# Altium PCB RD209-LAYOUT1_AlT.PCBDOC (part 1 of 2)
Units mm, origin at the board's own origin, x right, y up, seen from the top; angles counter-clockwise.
Board outline 152.4 x 152.4 mm, 4 copper layers (TOP, Mid-Layer 1, Mid-Layer 2, BOTTOM), stack 0.711 mm thick; 246 components, 168 nets, 761 pads, 266 vias.
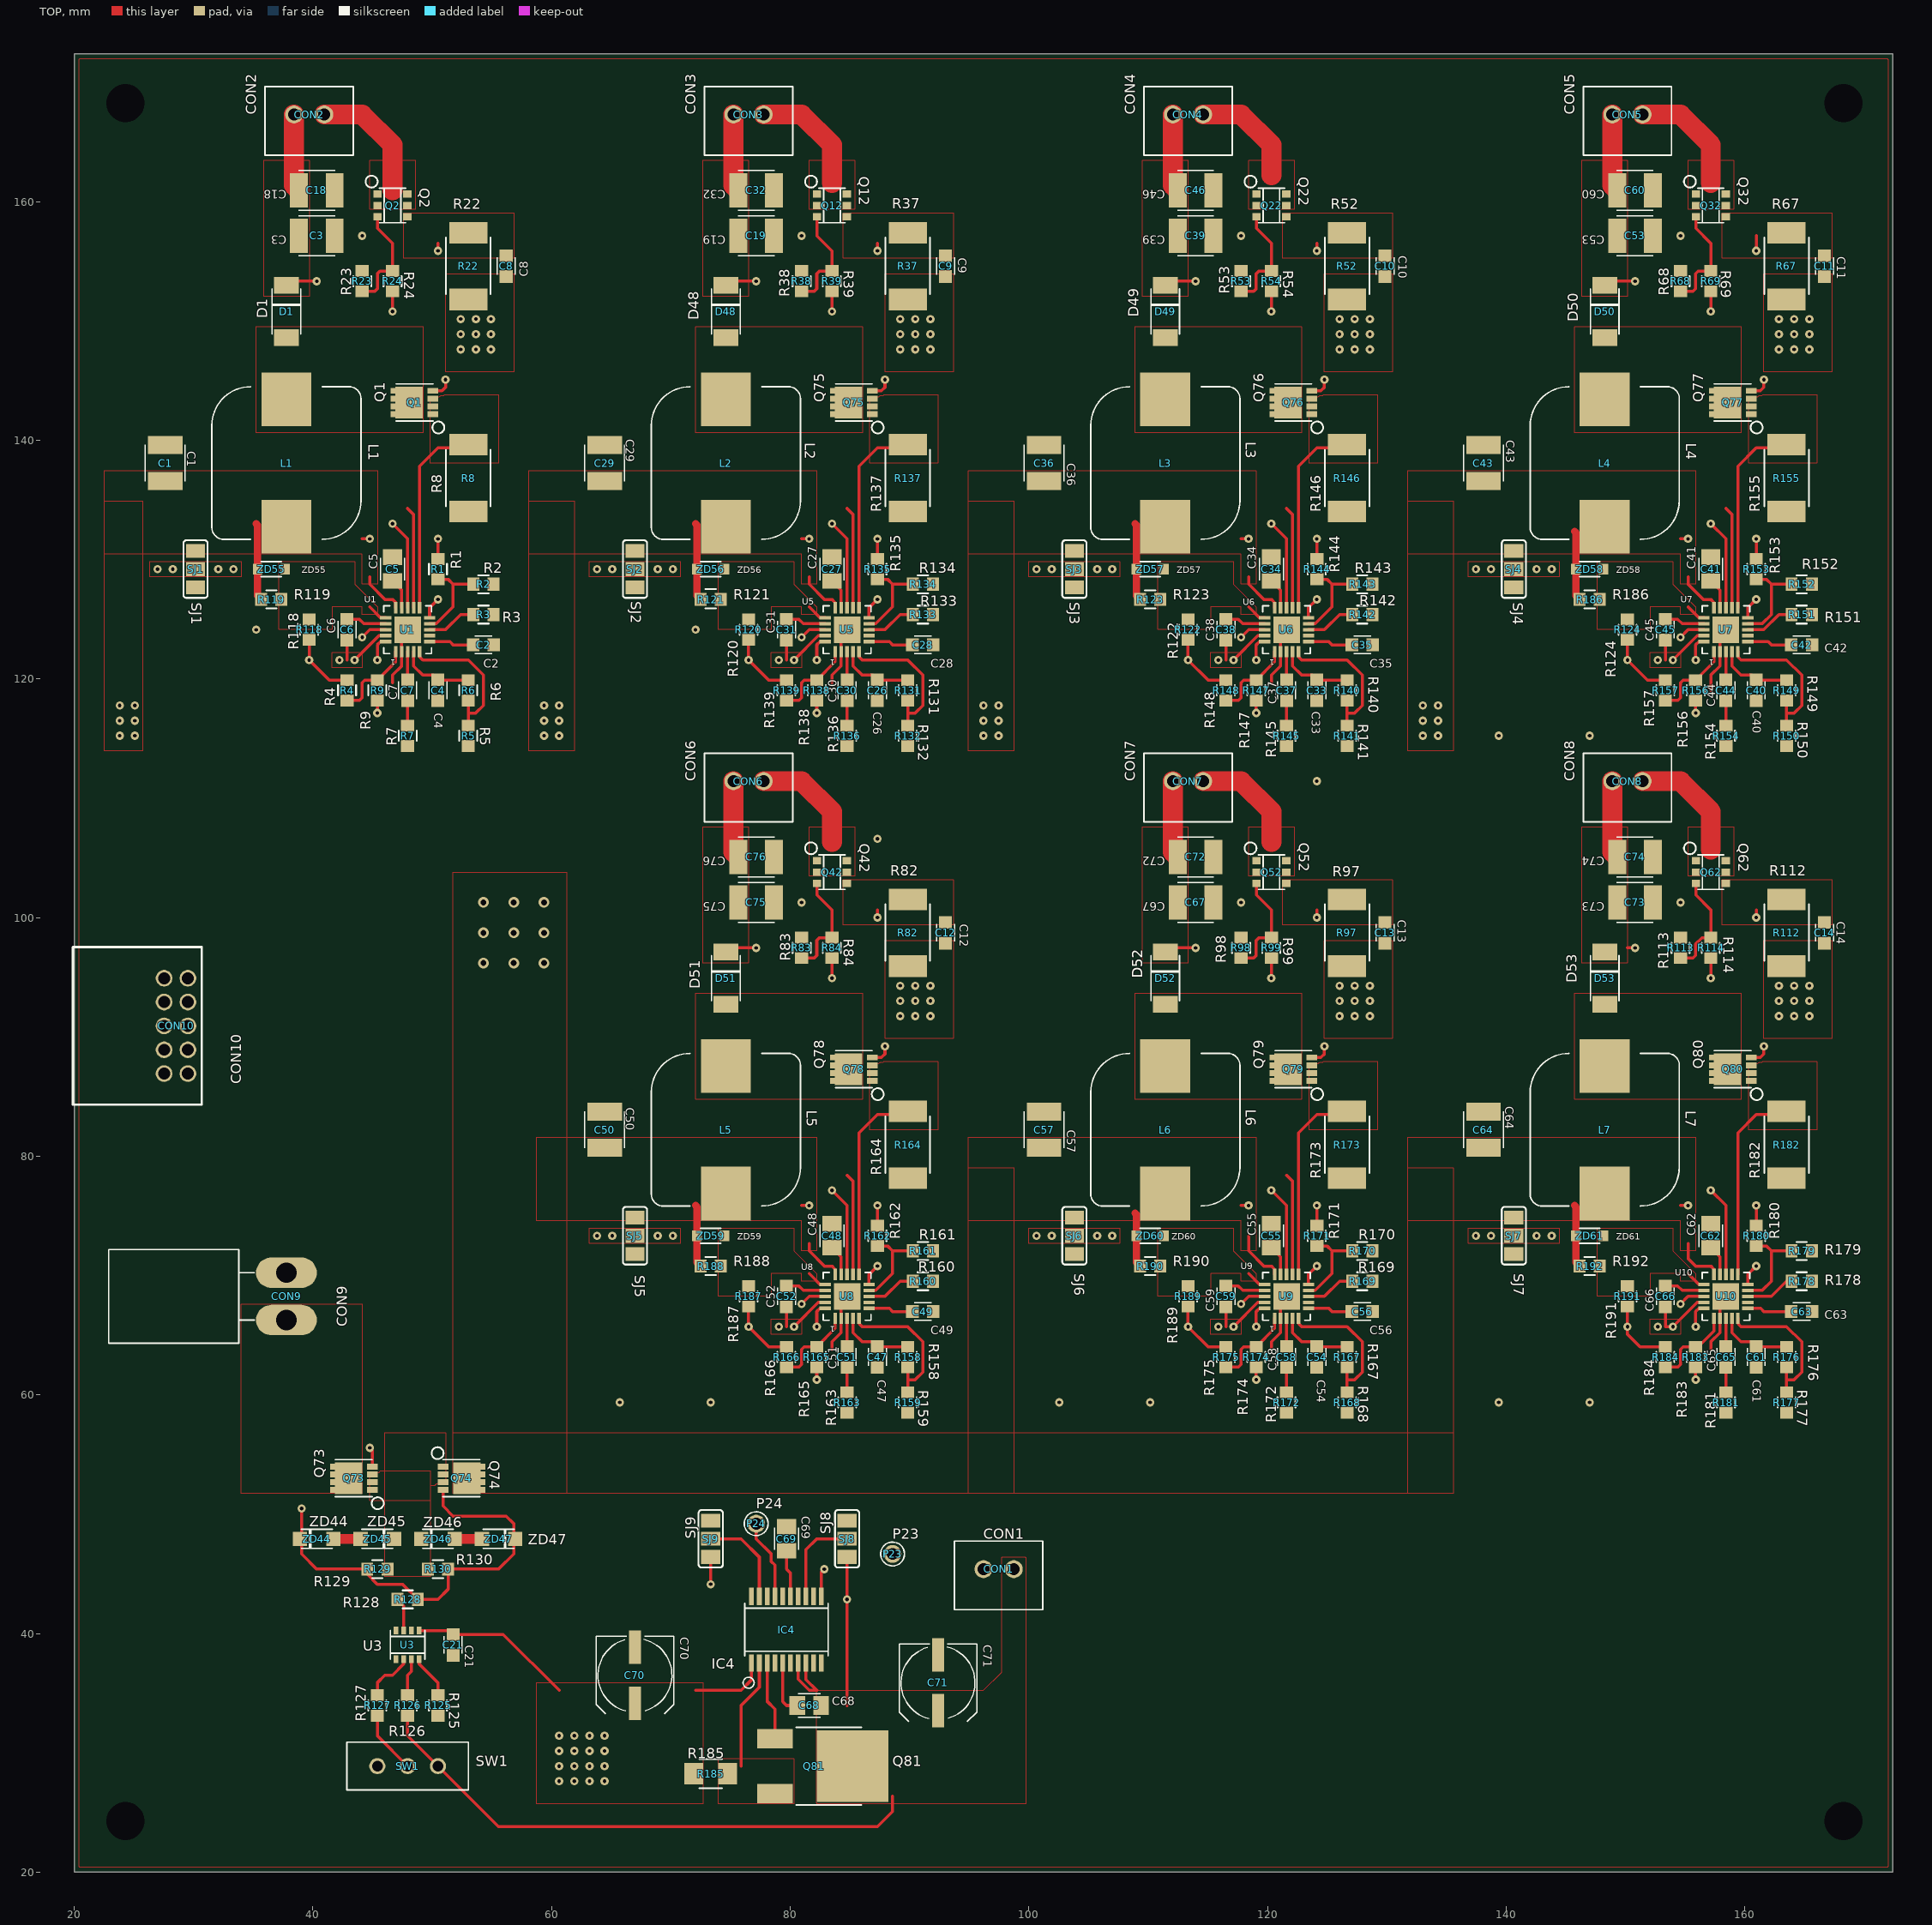
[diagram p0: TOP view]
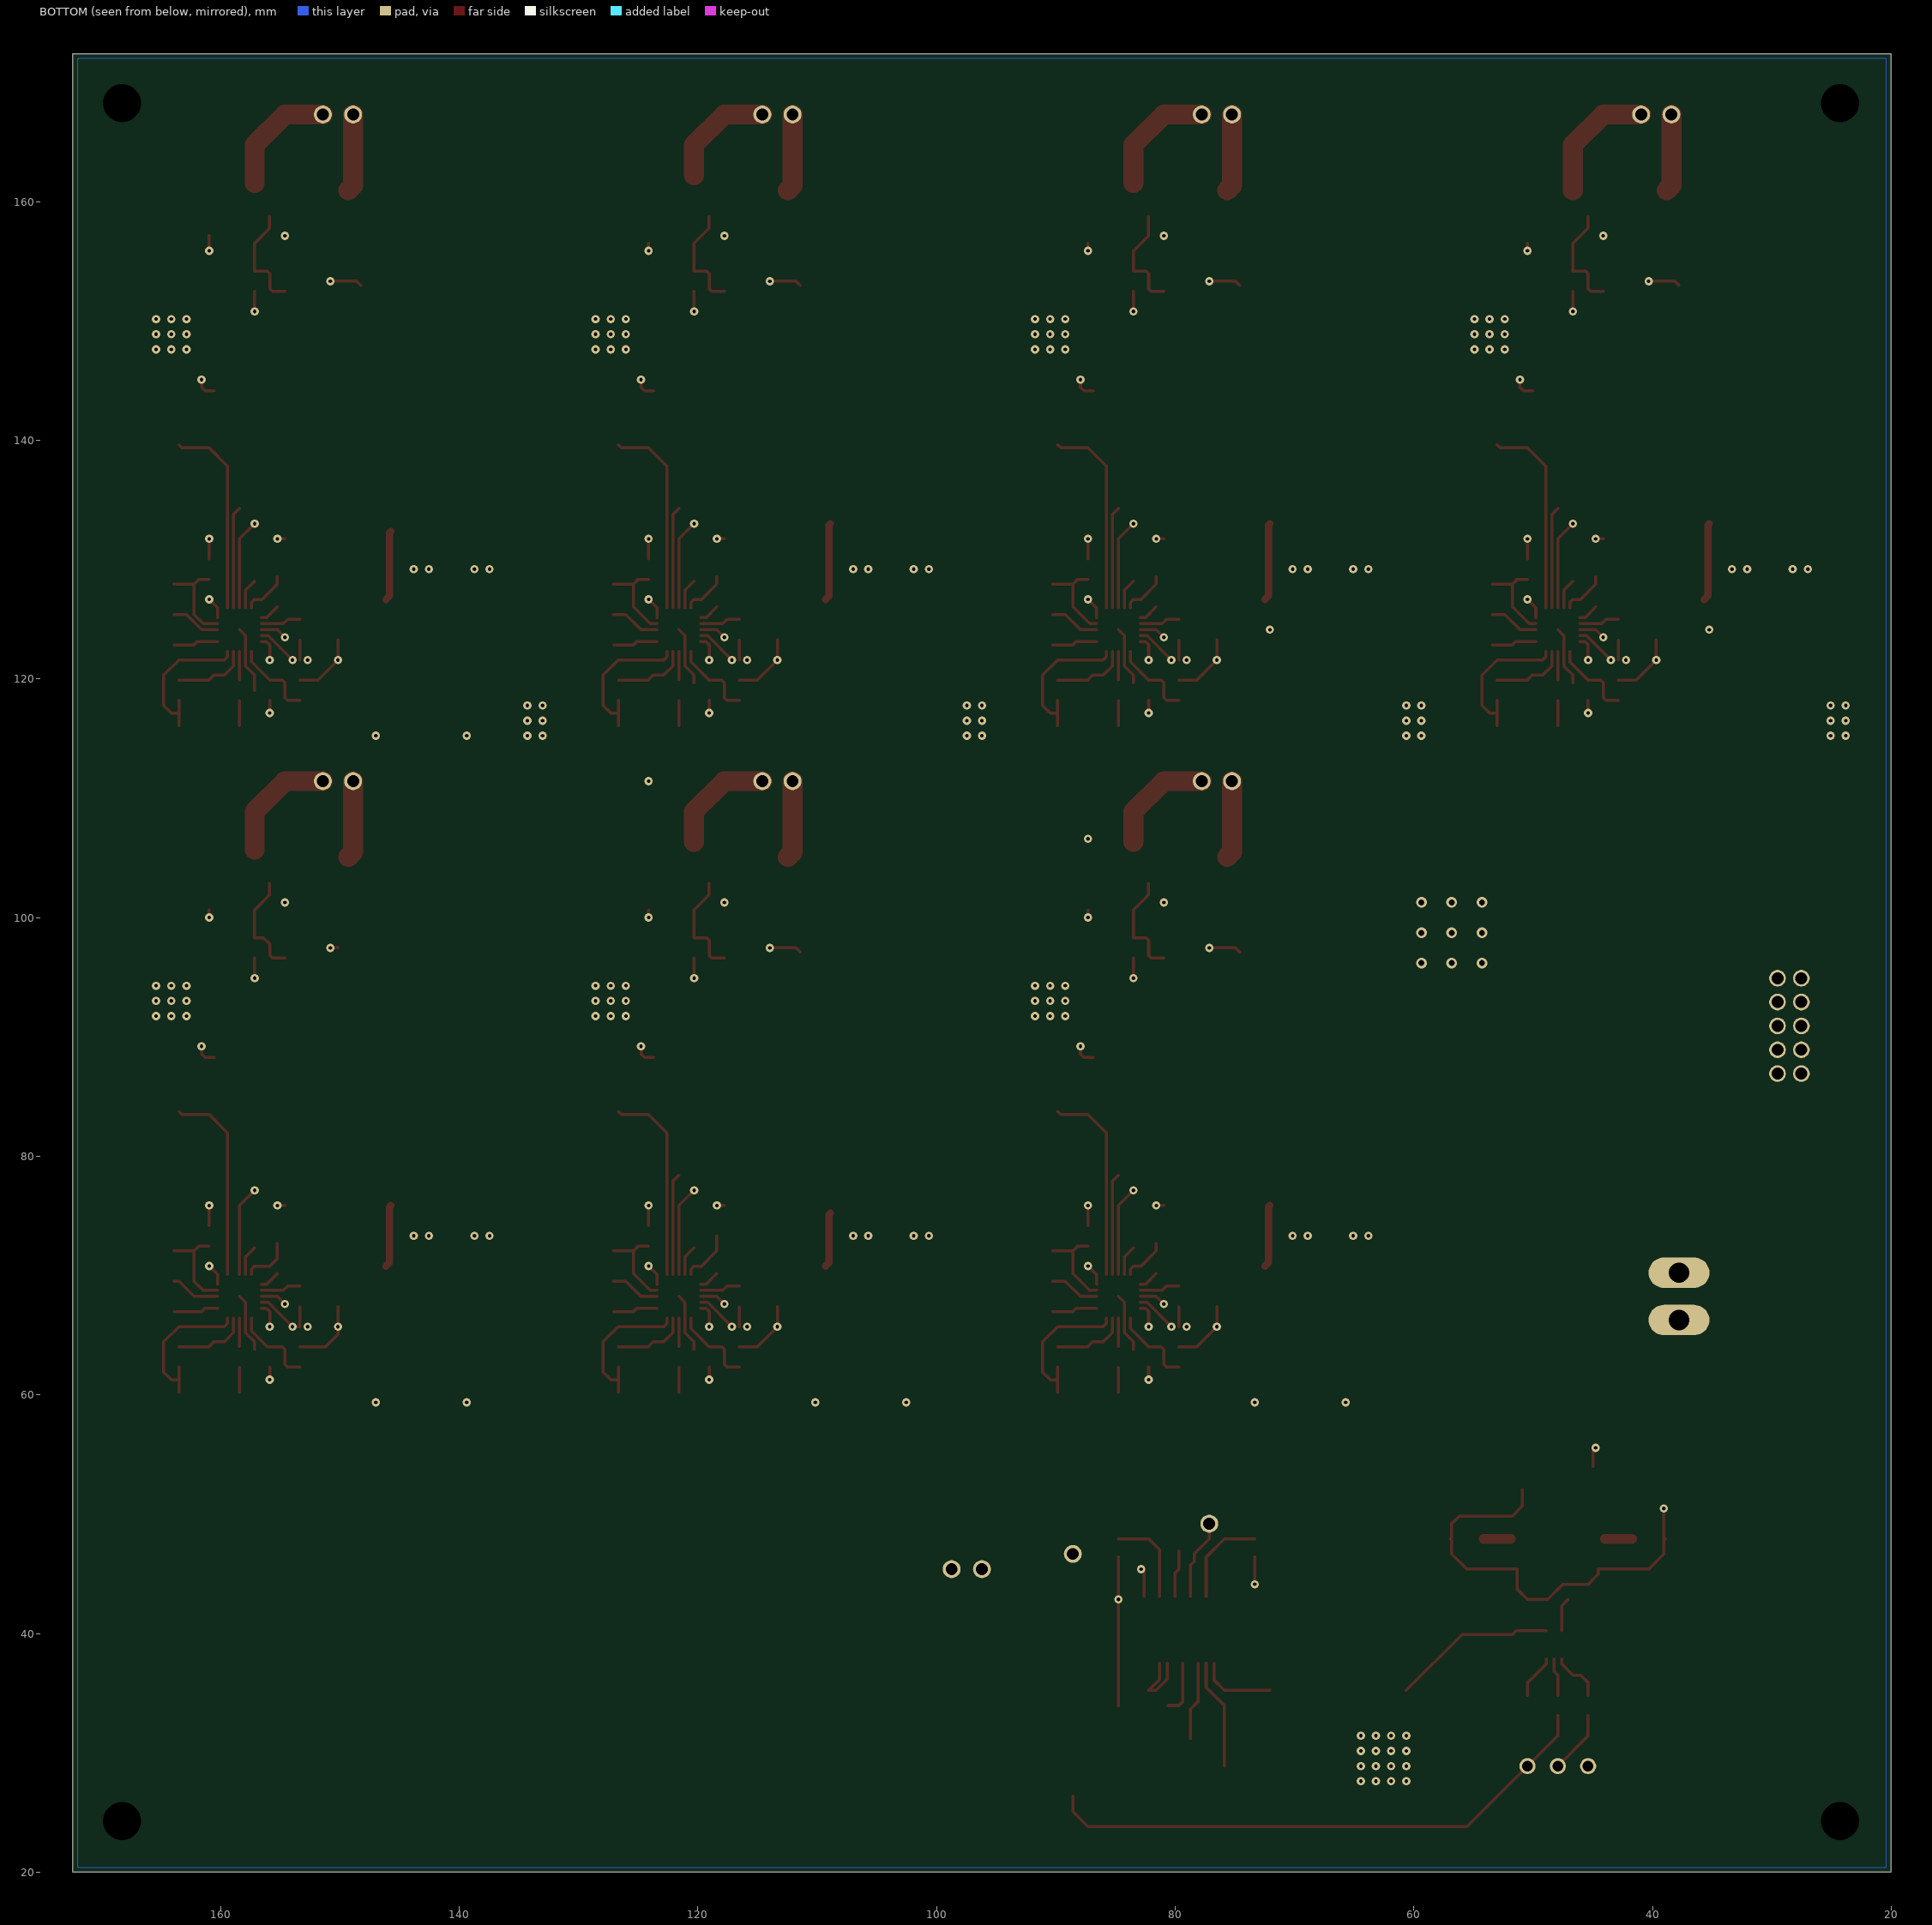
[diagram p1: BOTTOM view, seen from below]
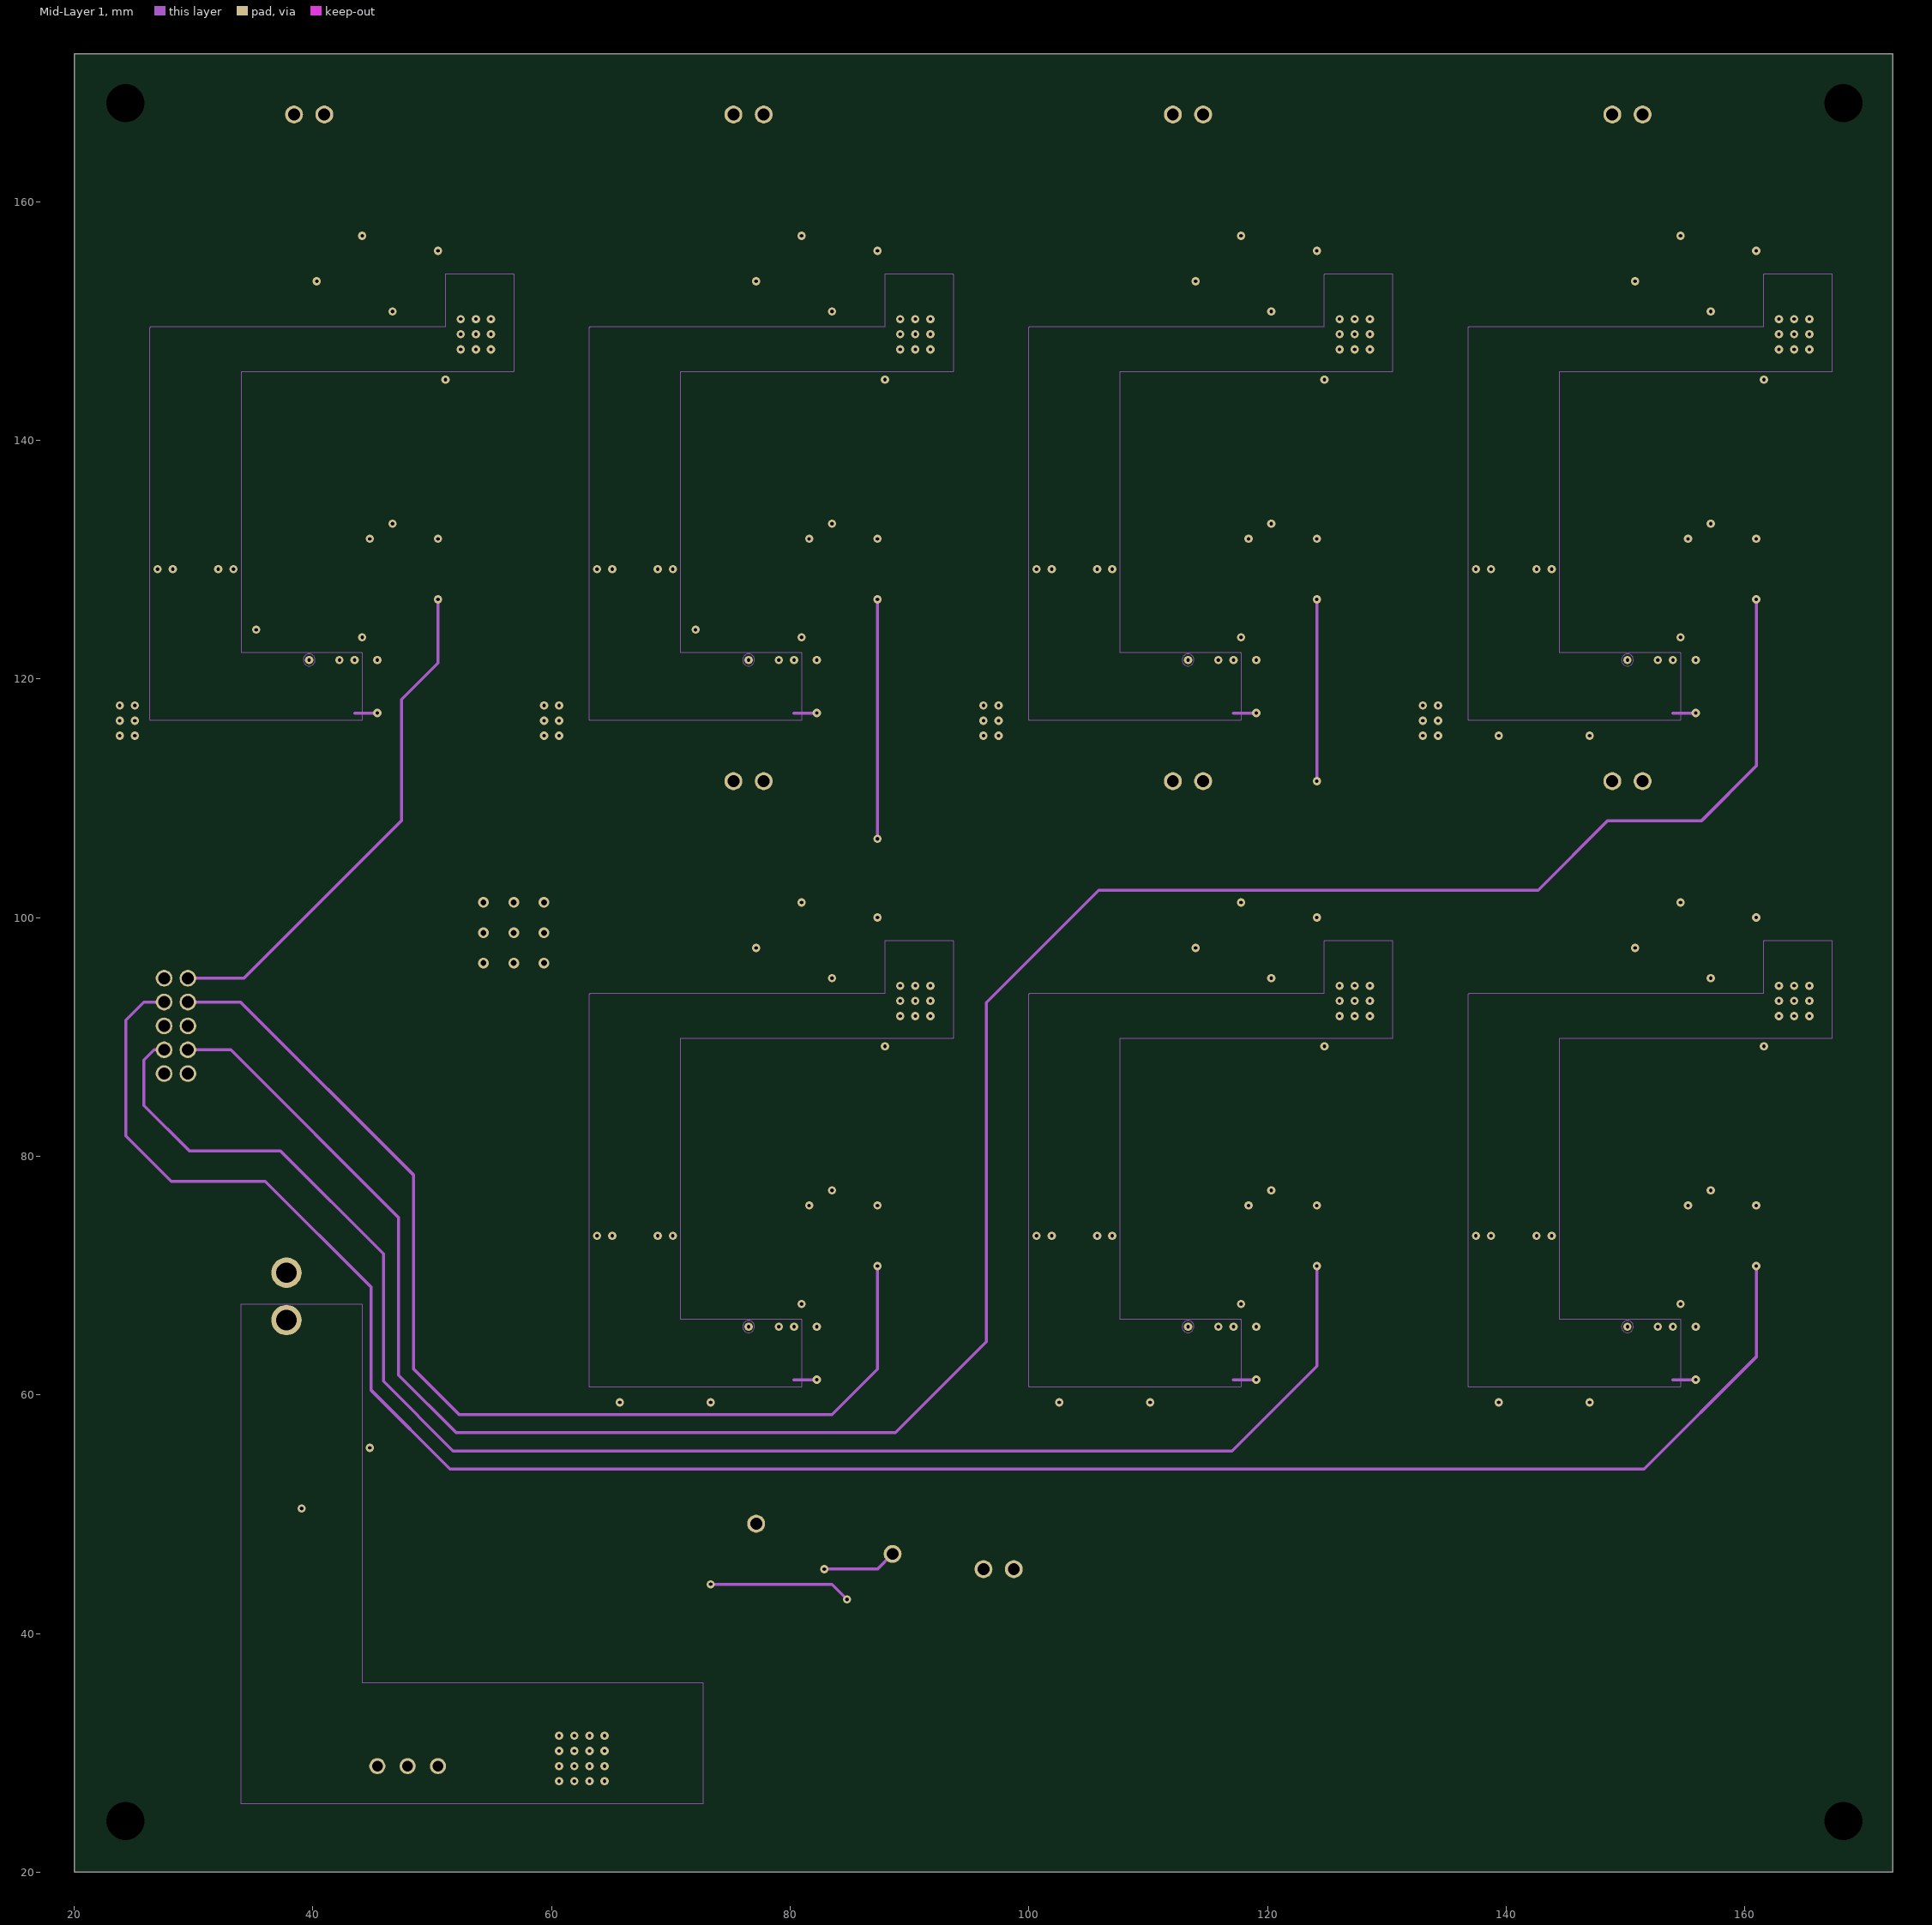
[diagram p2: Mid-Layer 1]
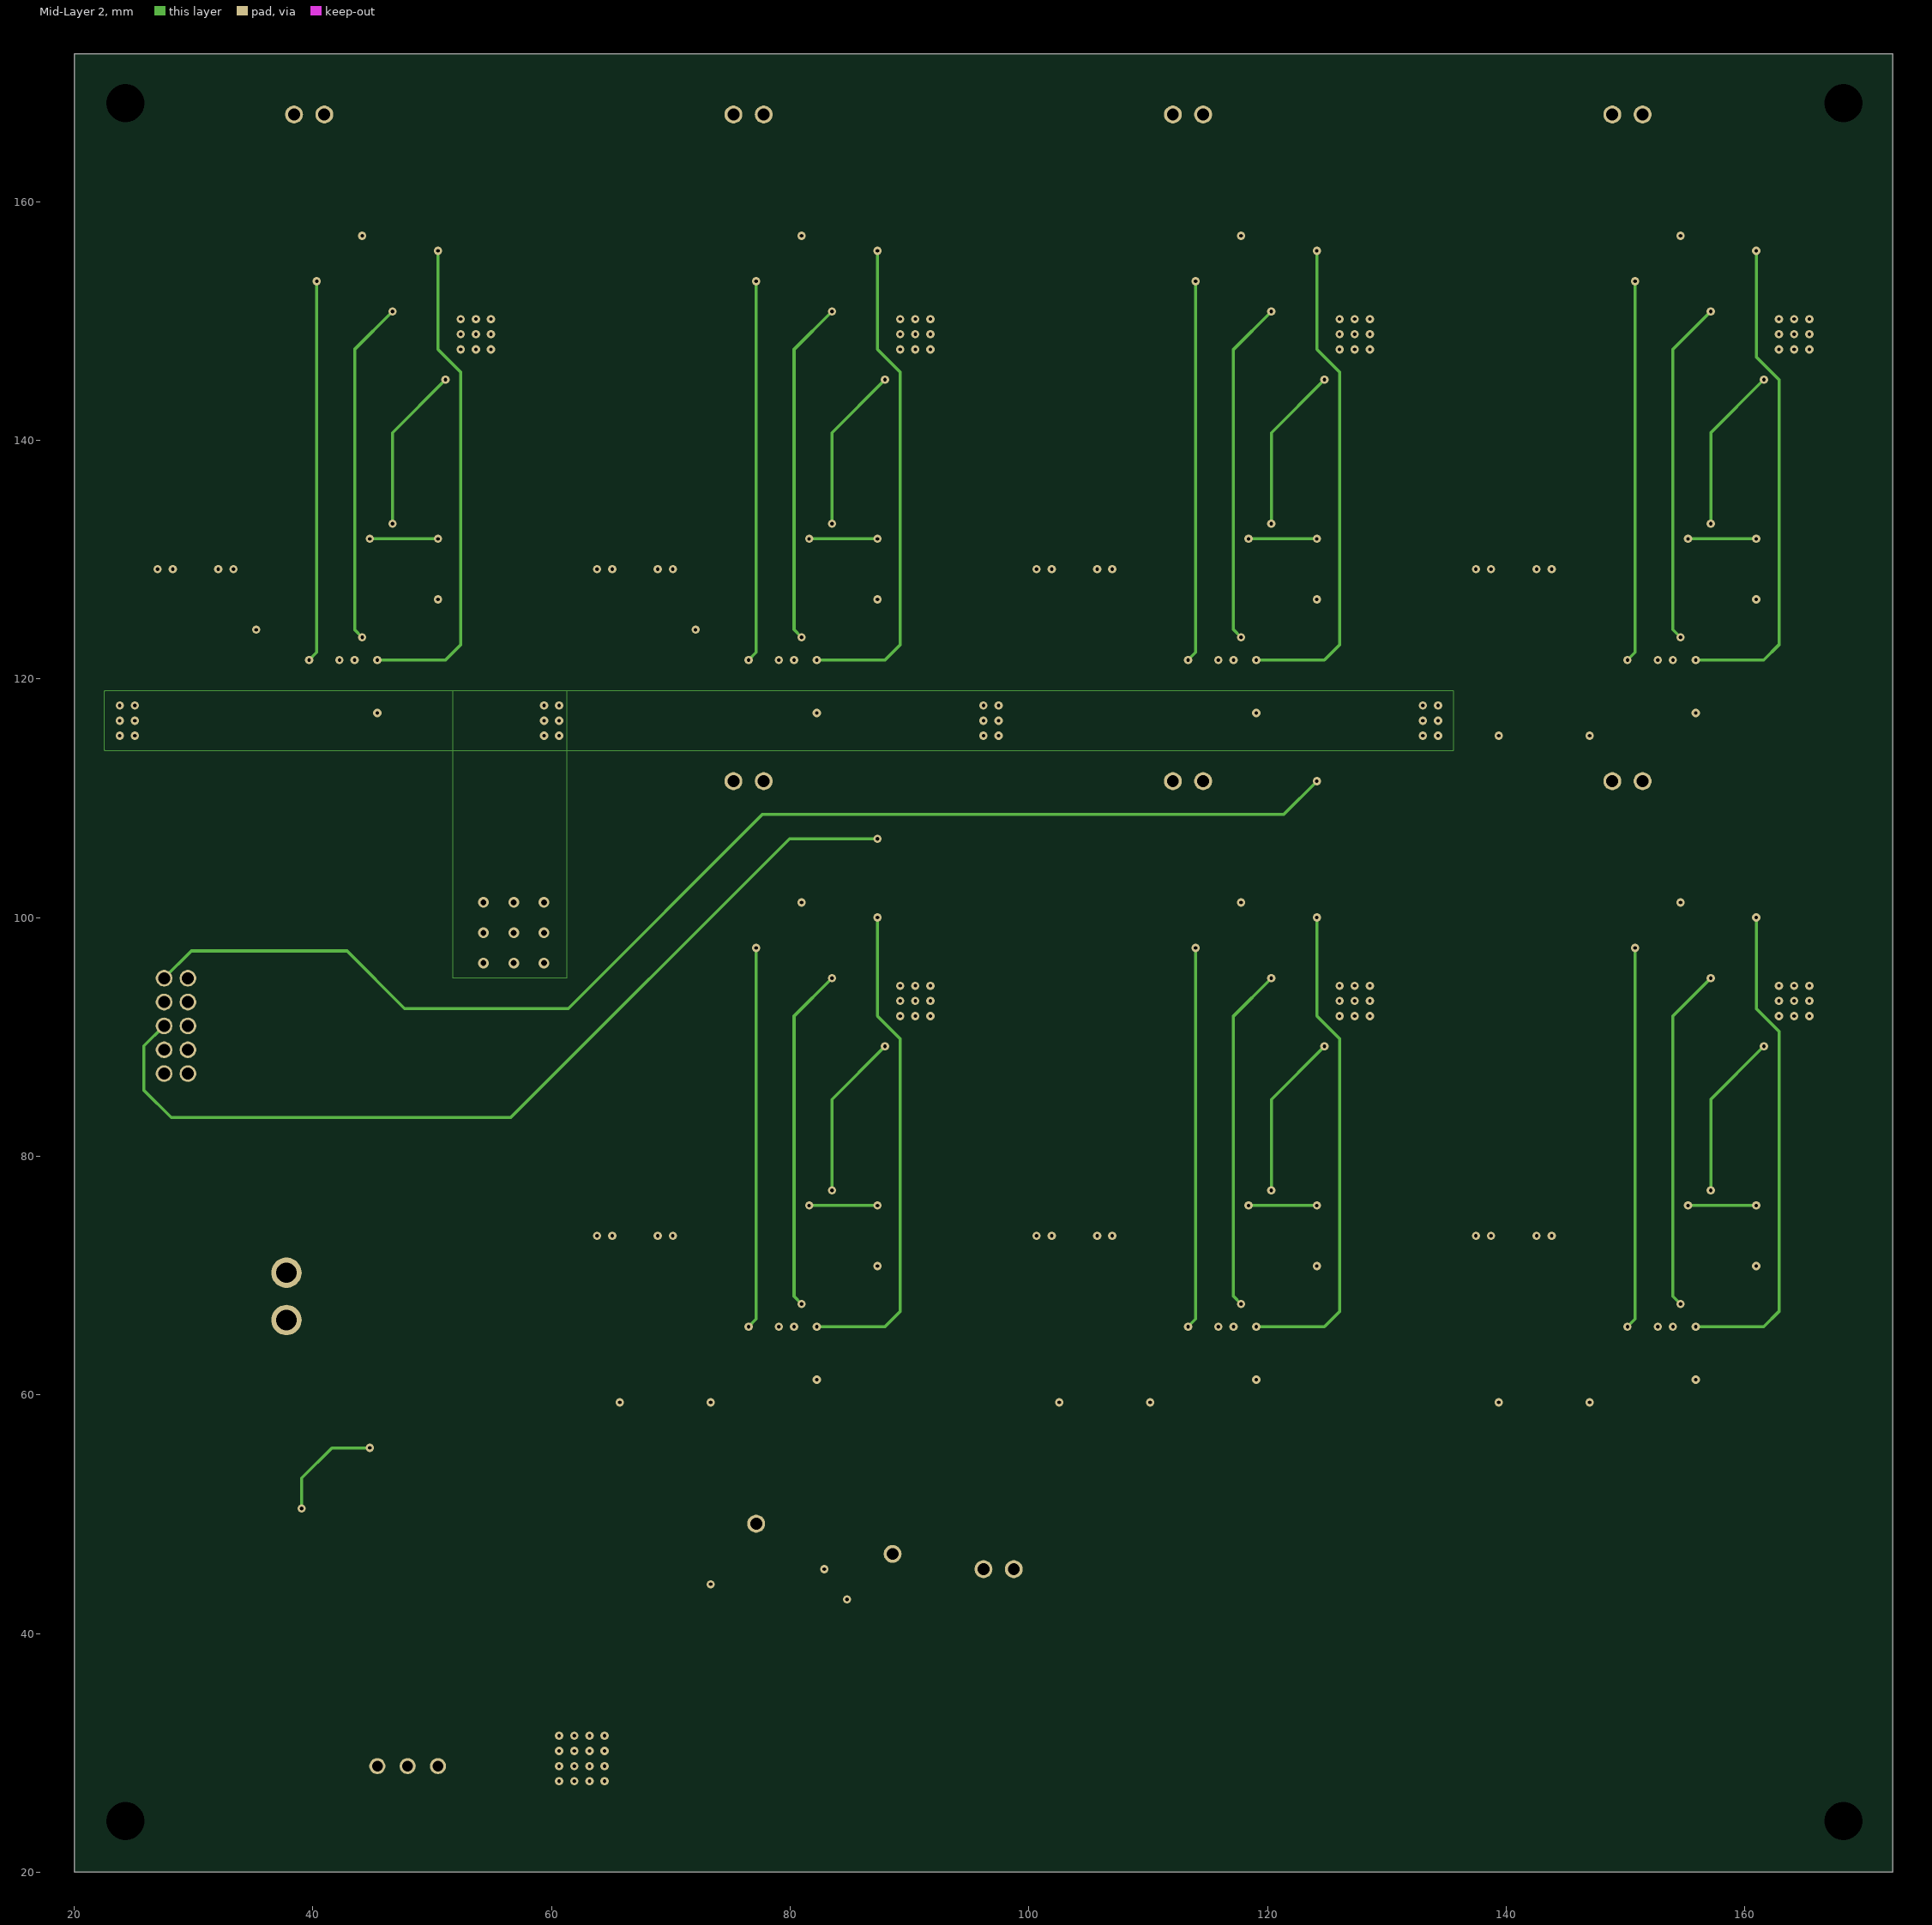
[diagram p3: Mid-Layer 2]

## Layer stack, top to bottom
Top Solder: solder mask 0.0102, Solder Resist, Dk 3.5
TOP: signal copper (thickness not stored)
Mid-Layer 1: signal copper 0.0356
Dielectric2: dielectric 0.32, FR-4, Dk 4.8
Mid-Layer 2: signal copper 0.0356
Dielectric3: dielectric 0.32, FR-4, Dk 4.8
BOTTOM: signal copper (thickness not stored)
Bottom Solder: solder mask 0.0102, Solder Resist, Dk 3.5

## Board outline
172.4,172.4 172.4,20 20,20 20,172.4

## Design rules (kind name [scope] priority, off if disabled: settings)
AssemblyTestPointUsage [All] p0: scope1count=1 scope1_0_kind=Board scope1_0_value=Board scope2count=1 scope2_0_kind=Board scope2_0_value=Board commentlength=0
AssemblyTestpoint [All] p0: scope1count=1 scope1_0_kind=Board scope1_0_value=Board scope2count=1 scope2_0_kind=Board scope2_0_value=Board commentlength=0
Clearance [All] p0: scope1count=1 scope1_0_kind=Board scope1_0_value=Board scope2count=1 scope2_0_kind=Board scope2_0_value=Board commentlength=0 gap=0.001
Clearance [All] p1: gap=0.001 ignorepadtopadclearanceinfootprint=TRUE except(0.15: Arc-Arc Arc-Track Arc-SMDPad Arc-THPad Arc-Via Arc-Fill Arc-Poly Arc-Region Arc-Text Track-Track Track-SMDPad Track-THPad Track-Via Track-Fill Track-Poly Track-Region Track-Text SMDPad-SMDPad SMDPad-THPad SMDPad-Via SMDPad-Fill SMDPad-Poly SMDPad-Region SMDPad-Text THPad-THPad THPad-Via THPad-Fill THPad-Poly THPad-Region THPad-Text Via-Via Via-Fill Via-Poly Via-Region Via-Text Fill-Fill Fill-Poly Fill-Region Fill-Text Poly-Poly Poly-Region Poly-Text Region-Region Region-Text Text-Text; 0.3: Arc-Hole Track-Hole SMDPad-Hole THPad-Hole Via-Hole Fill-Hole Poly-Hole Region-Hole Text-Hole)
ComponentClearance [All] p0: scope1count=1 scope1_0_kind=Board scope1_0_value=Board scope2count=1 scope2_0_kind=Board scope2_0_value=Board commentlength=0 gap=0.254 collisioncheckmode=3
DiffPairsRouting [All] p0: scope1count=1 scope1_0_kind=Board scope1_0_value=Board scope2count=1 scope2_0_kind=Board scope2_0_value=Board commentlength=0
FabricationTestPointUsage [All] p0: scope1count=1 scope1_0_kind=Board scope1_0_value=Board scope2count=1 scope2_0_kind=Board scope2_0_value=Board commentlength=0 valid=0 allowmultiple=FALSE
FabricationTestpoint [All] p0: scope1count=1 scope1_0_kind=Board scope1_0_value=Board scope2count=1 scope2_0_kind=Board scope2_0_value=Board commentlength=0 side=3 testpointundercomponent=TRUE minsize=1.016 maxsize=2.54 preferedsize=1.524 minholesize=0 maxholesize=1.016 preferedholesize=0.813 testpointgrid=0.025
FanoutControl Fanout_Default [All] p0: scope1count=1 scope1_0_kind=Board scope1_0_value=Board scope2count=1 scope2_0_kind=Board scope2_0_value=Board commentlength=30 // Fanout_Default (Default Rule)
FanoutControl Fanout_Small [All] p0 off: scope1count=1 scope1_0_kind=Board scope1_0_value=Board scope2count=1 scope2_0_kind=Board scope2_0_value=Board commentlength=84 // Protel DXP Scope 1 Expression Was: (CompPinCount < 5)   Fanout_Small (Default Rule)
FanoutControl Fanout_SOIC [All] p0 off: scope1count=1 scope1_0_kind=Board scope1_0_value=Board scope2count=1 scope2_0_kind=Board scope2_0_value=Board commentlength=71 // Protel DXP Scope 1 Expression Was: IsSOIC   Fanout_SOIC (Default Rule)
FanoutControl Fanout_LCC [All] p0 off: scope1count=1 scope1_0_kind=Board scope1_0_value=Board scope2count=1 scope2_0_kind=Board scope2_0_value=Board commentlength=69 // Protel DXP Scope 1 Expression Was: IsLCC   Fanout_LCC (Default Rule)
FanoutControl Fanout_BGA [All] p0 off: scope1count=1 scope1_0_kind=Board scope1_0_value=Board scope2count=1 scope2_0_kind=Board scope2_0_value=Board commentlength=69 // Protel DXP Scope 1 Expression Was: IsBGA   Fanout_BGA (Default Rule)
Height [All] p0: scope1count=1 scope1_0_kind=Board scope1_0_value=Board scope2count=1 scope2_0_kind=Board scope2_0_value=Board commentlength=0
HoleSize [All] p0: scope1count=1 scope1_0_kind=Board scope1_0_value=Board scope2count=1 scope2_0_kind=Board scope2_0_value=Board commentlength=0 absolutevalues=TRUE maxlimit=100 minlimit=0.001 maxpercent=80.000 minpercent=20.000
HoleSize [All] p1: absolutevalues=TRUE maxlimit=100 minlimit=0.001 maxpercent=80.000 minpercent=20.000
HoleToHoleClearance [All] p0: scope1count=1 scope1_0_kind=Board scope1_0_value=Board scope2count=1 scope2_0_kind=Board scope2_0_value=Board commentlength=0
HoleToHoleClearance [All] p1: gap=0.4 allowstackedmicrovias=FALSE
LayerPairs [All] p0: scope1count=1 scope1_0_kind=Board scope1_0_value=Board scope2count=1 scope2_0_kind=Board scope2_0_value=Board commentlength=0 enforce=TRUE
MinimumSolderMaskSliver [All] p0: scope1count=1 scope1_0_kind=Board scope1_0_value=Board scope2count=1 scope2_0_kind=Board scope2_0_value=Board commentlength=0
MinimumSolderMaskSliver [All] p1: minsoldermaskwidth=0.1
NetAntennae [All] p0: scope1count=1 scope1_0_kind=Board scope1_0_value=Board scope2count=1 scope2_0_kind=Board scope2_0_value=Board commentlength=0
NetAntennae [All] p1: netantennaetolerance=100
PasteMaskExpansion [All] p0: scope1count=1 scope1_0_kind=Board scope1_0_value=Board scope2count=1 scope2_0_kind=Board scope2_0_value=Board commentlength=0 expansion=0
PlaneClearance [All] p0: scope1count=1 scope1_0_kind=Board scope1_0_value=Board scope2count=1 scope2_0_kind=Board scope2_0_value=Board commentlength=0 clearance=0.001
PlaneClearance [All] p1: clearance=0.001
PlaneConnect [All] p0: scope1count=1 scope1_0_kind=Board scope1_0_value=Board scope2count=1 scope2_0_kind=Board scope2_0_value=Board commentlength=0 planeconnectstyle=Direct reliefexpansion=0.508 reliefentries=4 reliefconductorwidth=0.254 reliefairgap=0.254
PlaneConnect [All] p1: planeconnectstyle=Direct reliefexpansion=0.508 reliefentries=4 reliefconductorwidth=0.254 reliefairgap=0.254
PolygonConnect [All] p0: scope1count=1 scope1_0_kind=Board scope1_0_value=Board scope2count=1 scope2_0_kind=Board scope2_0_value=Board commentlength=0 connectstyle=Direct reliefconductorwidth=0.254 reliefentries=4 polygonreliefangle="90 Angle"
PolygonConnect [All] p1: connectstyle=Direct reliefconductorwidth=0.254 reliefentries=4 polygonreliefangle="90 Angle" airgapwidth=0.254
RoutingCorners [All] p0: scope1count=1 scope1_0_kind=Board scope1_0_value=Board scope2count=1 scope2_0_kind=Board scope2_0_value=Board commentlength=0 cornerstyle=45-Degree minsetback=2.54 maxsetback=2.54
RoutingLayers [All] p0: scope1count=1 scope1_0_kind=Board scope1_0_value=Board scope2count=1 scope2_0_kind=Board scope2_0_value=Board commentlength=0 top layer=Automatic mid layer 1=Automatic mid layer 2=Automatic bottom layer=Automatic
RoutingPriority [All] p0: scope1count=1 scope1_0_kind=Board scope1_0_value=Board scope2count=1 scope2_0_kind=Board scope2_0_value=Board commentlength=0
RoutingTopology [All] p0: scope1count=1 scope1_0_kind=Board scope1_0_value=Board scope2count=1 scope2_0_kind=Board scope2_0_value=Board commentlength=0 topology=Shortest
RoutingVias [All] p0: scope1count=1 scope1_0_kind=Board scope1_0_value=Board scope2count=1 scope2_0_kind=Board scope2_0_value=Board commentlength=0 holewidth=0.1 width=0.1 viastyle="Through Hole" minholewidth=0.001 minwidth=0.001 maxholewidth=100 maxwidth=100
RoutingVias [All] p1: holewidth=0.1 width=0.1 viastyle="Through Hole" minholewidth=0.001 minwidth=0.001 maxholewidth=100 maxwidth=100
ShortCircuit [All] p0: scope1count=1 scope1_0_kind=Board scope1_0_value=Board scope2count=1 scope2_0_kind=Board scope2_0_value=Board commentlength=0 allowed=FALSE
SilkToBoardRegionClearance [All] p0: scope1count=1 scope1_0_kind=Board scope1_0_value=Board scope2count=1 scope2_0_kind=Board scope2_0_value=Board commentlength=0
SilkToSilkClearance [All] p0: scope1count=1 scope1_0_kind=Board scope1_0_value=Board scope2count=1 scope2_0_kind=Board scope2_0_value=Board commentlength=0
SilkToSilkClearance [All] p1: silktosilkclearance=0.001
SilkToSolderMaskClearance [All] p0 off: scope1count=1 scope1_0_kind=Board scope1_0_value=Board scope2count=1 scope2_0_kind=Board scope2_0_value=Board commentlength=44 // Protel DXP Scope 1 Expression Was: IsPad
SilkToSolderMaskClearance [IsPad] p1: minsilkscreentomaskgap=0 clearancetoexposedcopper=TRUE
SolderMaskExpansion [All] p0: scope1count=1 scope1_0_kind=Board scope1_0_value=Board scope2count=1 scope2_0_kind=Board scope2_0_value=Board commentlength=0 expansion=0.001
SolderMaskExpansion [All] p1: expansion=0.001
UnRoutedNet [All] p0: scope1count=1 scope1_0_kind=Board scope1_0_value=Board scope2count=1 scope2_0_kind=Board scope2_0_value=Board commentlength=0
UnpouredPolygon [All] p0: scope1count=1 scope1_0_kind=Board scope1_0_value=Board scope2count=1 scope2_0_kind=Board scope2_0_value=Board commentlength=0
UnpouredPolygon [All] p0: scope1count=1 scope1_0_kind=Board scope1_0_value=Board scope2count=1 scope2_0_kind=Board scope2_0_value=Board commentlength=0
Width [All] p0: scope1count=1 scope1_0_kind=Board scope1_0_value=Board scope2count=1 scope2_0_kind=Board scope2_0_value=Board commentlength=0 maxlimit=1000 minlimit=2539.975 preferedwidth=0
Width [All] p1: maxlimit=1000 minlimit=2539.975 preferedwidth=0 toplayer_minwidth=0 midlayer1_minwidth=0 midlayer2_minwidth=0 bottomlayer_minwidth=0 minimp=50.000000 maximp=50.000000 favimp=50.000000
22 further rules are at their usual default settings.

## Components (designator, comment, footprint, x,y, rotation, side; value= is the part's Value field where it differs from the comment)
C1 "C1210K" C1210K 27.62,138.11 r270 top
C2 "C0603K" C0603K 54.29,122.87 r180 top
C3 "C1210K" C1210K 40.32,157.16 r180 top
C4 "C0603K" C0603K 50.48,119.06 r90 top
C5 "C0805K" C0805K 46.67,129.22 r270 top
C6 "C0603K" C0603K 42.86,124.14 r90 top
C7 "C0603K" C0603K 47.94,119.06 r90 top
C8 "C0603K" C0603K 56.195,154.62 r90 top
C9 "C0603K" C0603K 93.025,154.62 r90 top
C10 "C0603K" C0603K 129.855,154.62 r90 top
C11 "C0603K" C0603K 166.685,154.62 r90 top
C12 "C0603K" C0603K 93.025,98.74 r90 top
C13 "C0603K" C0603K 129.855,98.74 r90 top
C14 "C0603K" C0603K 166.685,98.74 r90 top
C18 "C1210K" C1210K 40.32,160.97 r180 top
C19 "C1210K" C1210K 77.15,157.16 r180 top
C21 "C0603K" C0603K 51.75,39.05 r270 top
C26 "C0603K" C0603K 87.31,119.06 r90 top
C27 "C0805K" C0805K 83.5,129.22 r270 top
C28 "C0603K" C0603K 91.12,122.87 r180 top
C29 "C1210K" C1210K 64.45,138.11 r270 top
C30 "C0603K" C0603K 84.77,119.06 r90 top
C31 "C0603K" C0603K 79.69,124.14 r90 top
C32 "C1210K" C1210K 77.15,160.97 r180 top
C33 "C0603K" C0603K 124.14,119.06 r90 top
C34 "C0805K" C0805K 120.33,129.22 r270 top
C35 "C0603K" C0603K 127.95,122.87 r180 top
C36 "C1210K" C1210K 101.28,138.11 r270 top
C37 "C0603K" C0603K 121.6,119.06 r90 top
C38 "C0603K" C0603K 116.52,124.14 r90 top
C39 "C1210K" C1210K 113.98,157.16 r180 top
C40 "C0603K" C0603K 160.97,119.06 r90 top
C41 "C0805K" C0805K 157.16,129.22 r270 top
C42 "C0603K" C0603K 164.78,122.87 r180 top
C43 "C1210K" C1210K 138.11,138.11 r270 top
C44 "C0603K" C0603K 158.43,119.06 r90 top
C45 "C0603K" C0603K 153.35,124.14 r90 top
C46 "C1210K" C1210K 113.98,160.97 r180 top
C47 "C0603K" C0603K 87.31,63.18 r90 top
C48 "C0805K" C0805K 83.5,73.34 r270 top
C49 "C0603K" C0603K 91.12,66.99 r180 top
C50 "C1210K" C1210K 64.45,82.23 r270 top
C51 "C0603K" C0603K 84.77,63.18 r90 top
C52 "C0603K" C0603K 79.69,68.26 r90 top
C53 "C1210K" C1210K 150.81,157.16 r180 top
C54 "C0603K" C0603K 124.14,63.18 r90 top
C55 "C0805K" C0805K 120.33,73.34 r270 top
C56 "C0603K" C0603K 127.95,66.99 r180 top
C57 "C1210K" C1210K 101.28,82.23 r270 top
C58 "C0603K" C0603K 121.6,63.18 r90 top
C59 "C0603K" C0603K 116.52,68.26 r90 top
C60 "C1210K" C1210K 150.81,160.97 r180 top
C61 "C0603K" C0603K 160.97,63.18 r90 top
C62 "C0805K" C0805K 157.16,73.34 r270 top
C63 "C0603K" C0603K 164.78,66.99 r180 top
C64 "C1210K" C1210K 138.11,82.23 r270 top
C65 "C0603K" C0603K 158.43,63.18 r90 top
C66 "C0603K" C0603K 153.35,68.26 r90 top
C67 "C1210K" C1210K 113.98,101.28 r180 top
C68 "C0805K" C0805K 81.595,33.97 r180 top
C69 "C0805K" C0805K 79.69,47.94 r90 top
C70 "UD-6_3X5_8_NICHICON" UD-6_3X5_8_NICHICON 66.99,36.51 r270 top
C71 "UD-6_3X5_8_NICHICON" UD-6_3X5_8_NICHICON 92.39,35.875 r270 top
C72 "C1210K" C1210K 113.98,105.09 r180 top
C73 "C1210K" C1210K 150.81,101.28 r180 top
C74 "C1210K" C1210K 150.81,105.09 r180 top
C75 "C1210K" C1210K 77.15,101.28 r180 top
C76 "C1210K" C1210K 77.15,105.09 r180 top
CON1 "B2B-XH-A" B2B-XH-A 97.47,45.4 r180 top
CON2 "B2B-XH-A" B2B-XH-A 39.685,167.32 r180 top
CON3 "B2B-XH-A" B2B-XH-A 76.515,167.32 r180 top
CON4 "B2B-XH-A" B2B-XH-A 113.345,167.32 r180 top
CON5 "B2B-XH-A" B2B-XH-A 150.175,167.32 r180 top
CON6 "B2B-XH-A" B2B-XH-A 76.515,111.44 r180 top
CON7 "B2B-XH-A" B2B-XH-A 113.345,111.44 r180 top
CON8 "B2B-XH-A" B2B-XH-A 150.175,111.44 r180 top
CON9 "B2PS-VH" B2PS-VH 37.78,68.26 r90 top
CON10 "CTK03280ATP" CTK03280ATP 29.525,94.93 r270 top
D1 "M-FLAT" M-FLAT 37.78,150.81 r90 top
D48 "M-FLAT" M-FLAT 74.61,150.81 r90 top
D49 "M-FLAT" M-FLAT 111.44,150.81 r90 top
D50 "M-FLAT" M-FLAT 148.27,150.81 r90 top
D51 "M-FLAT" M-FLAT 74.61,94.93 r90 top
D52 "M-FLAT" M-FLAT 111.44,94.93 r90 top
D53 "M-FLAT" M-FLAT 148.27,94.93 r90 top
IC4 "TB9005FNG" TB9005FNG 79.69,40.32 r0 top
L1 "CLF12577NI-D" CLF12577NI-D 37.78,138.11 r90 top
L2 "CLF12577NI-D" CLF12577NI-D 74.61,138.11 r90 top
L3 "CLF12577NI-D" CLF12577NI-D 111.44,138.11 r90 top
L4 "CLF12577NI-D" CLF12577NI-D 148.27,138.11 r90 top
L5 "CLF12577NI-D" CLF12577NI-D 74.61,82.23 r90 top
L6 "CLF12577NI-D" CLF12577NI-D 111.44,82.23 r90 top
L7 "CLF12577NI-D" CLF12577NI-D 148.27,82.23 r90 top
P23 "CT" CT 88.58,46.67 r270 top
P24 "CT" CT 77.15,49.21 r270 top
Q1 "TSON_ADVANCE_WF_" TSON_ADVANCE_WF_ 49.21,143.19 r90 top
Q2 "TSOP6F" TSOP6F 46.67,159.7 r270 top
Q12 "TSOP6F" TSOP6F 83.5,159.7 r270 top
Q22 "TSOP6F" TSOP6F 120.33,159.7 r270 top
Q32 "TSOP6F" TSOP6F 157.16,159.7 r270 top
Q42 "TSOP6F" TSOP6F 83.5,103.82 r270 top
Q52 "TSOP6F" TSOP6F 120.33,103.82 r270 top
Q62 "TSOP6F" TSOP6F 157.16,103.82 r270 top
Q73 "TSON_ADVANCE_WF_" TSON_ADVANCE_WF_ 44.13,53.02 r90 top
Q74 "TSON_ADVANCE_WF_" TSON_ADVANCE_WF_ 51.75,53.02 r270 top
Q75 "TSON_ADVANCE_WF_" TSON_ADVANCE_WF_ 86.04,143.19 r90 top
Q76 "TSON_ADVANCE_WF_" TSON_ADVANCE_WF_ 122.87,143.19 r90 top
Q77 "TSON_ADVANCE_WF_" TSON_ADVANCE_WF_ 159.7,143.19 r90 top
Q78 "TSON_ADVANCE_WF_" TSON_ADVANCE_WF_ 86.04,87.31 r90 top
Q79 "TSON_ADVANCE_WF_" TSON_ADVANCE_WF_ 122.87,87.31 r90 top
Q80 "TSON_ADVANCE_WF_" TSON_ADVANCE_WF_ 159.7,87.31 r90 top
Q81 "TTA005" TTA005 82.23,28.89 r270 top
R1 "R0603" R0603 50.48,129.22 r90 top
R2 "R0603" R0603 54.29,127.95 r180 top
R3 "R0603" R0603 54.29,125.41 r0 top
R4 "R0603" R0603 42.86,119.06 r90 top
R5 "R0603" R0603 53.02,115.25 r270 top
R6 "R0603" R0603 53.02,119.06 r90 top
R7 "R0603" R0603 47.94,115.25 r90 top
R8 "R2512" R2512 53.02,136.84 r90 top
R9 "R0603" R0603 45.4,119.06 r90 top
R22 "R2512" R2512 53.02,154.62 r90 top
R23 "R0603" R0603 44.13,153.35 r270 top
R24 "R0603" R0603 46.67,153.35 r270 top
R37 "R2512" R2512 89.85,154.62 r90 top
R38 "R0603" R0603 80.96,153.35 r270 top
R39 "R0603" R0603 83.5,153.35 r270 top
R52 "R2512" R2512 126.68,154.62 r90 top
R53 "R0603" R0603 117.79,153.35 r270 top
R54 "R0603" R0603 120.33,153.35 r270 top
R67 "R2512" R2512 163.51,154.62 r90 top
R68 "R0603" R0603 154.62,153.35 r270 top
R69 "R0603" R0603 157.16,153.35 r270 top
R82 "R2512" R2512 89.85,98.74 r90 top
R83 "R0603" R0603 80.96,97.47 r270 top
R84 "R0603" R0603 83.5,97.47 r270 top
R97 "R2512" R2512 126.68,98.74 r90 top
R98 "R0603" R0603 117.79,97.47 r270 top
R99 "R0603" R0603 120.33,97.47 r270 top
R112 "R2512" R2512 163.51,98.74 r90 top
R113 "R0603" R0603 154.62,97.47 r270 top
R114 "R0603" R0603 157.16,97.47 r270 top
R118 "R0603" R0603 39.685,124.14 r270 top
R119 "R0603" R0603 36.51,126.68 r180 top
R120 "R0603" R0603 76.515,124.14 r270 top
R121 "R0603" R0603 73.34,126.68 r180 top
R122 "R0603" R0603 113.345,124.14 r270 top
R123 "R0603" R0603 110.17,126.68 r180 top
R124 "R0603" R0603 150.175,124.14 r270 top
R125 "R0603" R0603 50.48,33.97 r90 top
R126 "R0603" R0603 47.94,33.97 r270 top
R127 "R0603" R0603 45.4,33.97 r90 top
R128 "R0603" R0603 47.94,42.86 r0 top
R129 "R0603" R0603 45.4,45.4 r180 top
R130 "R0603" R0603 50.48,45.4 r180 top
R131 "R0603" R0603 89.85,119.06 r90 top
R132 "R0603" R0603 89.85,115.25 r270 top
R133 "R0603" R0603 91.12,125.41 r0 top
R134 "R0603" R0603 91.12,127.95 r180 top
R135 "R0603" R0603 87.31,129.22 r90 top
R136 "R0603" R0603 84.77,115.25 r90 top
R137 "R2512" R2512 89.85,136.84 r90 top
R138 "R0603" R0603 82.23,119.06 r90 top
R139 "R0603" R0603 79.69,119.06 r90 top
R140 "R0603" R0603 126.68,119.06 r90 top
R141 "R0603" R0603 126.68,115.25 r270 top
R142 "R0603" R0603 127.95,125.41 r0 top
R143 "R0603" R0603 127.95,127.95 r180 top
R144 "R0603" R0603 124.14,129.22 r90 top
R145 "R0603" R0603 121.6,115.25 r90 top
R146 "R2512" R2512 126.68,136.84 r90 top
R147 "R0603" R0603 119.06,119.06 r90 top
R148 "R0603" R0603 116.52,119.06 r90 top
R149 "R0603" R0603 163.51,119.06 r90 top
R150 "R0603" R0603 163.51,115.25 r270 top
R151 "R0603" R0603 164.78,125.41 r0 top
R152 "R0603" R0603 164.78,127.95 r180 top
R153 "R0603" R0603 160.97,129.22 r90 top
R154 "R0603" R0603 158.43,115.25 r90 top
R155 "R2512" R2512 163.51,136.84 r90 top
R156 "R0603" R0603 155.89,119.06 r90 top
R157 "R0603" R0603 153.35,119.06 r90 top
R158 "R0603" R0603 89.85,63.18 r90 top
R159 "R0603" R0603 89.85,59.37 r270 top
R160 "R0603" R0603 91.12,69.53 r0 top
R161 "R0603" R0603 91.12,72.07 r180 top
R162 "R0603" R0603 87.31,73.34 r90 top
R163 "R0603" R0603 84.77,59.37 r90 top
R164 "R2512" R2512 89.85,80.96 r90 top
R165 "R0603" R0603 82.23,63.18 r90 top
R166 "R0603" R0603 79.69,63.18 r90 top
R167 "R0603" R0603 126.68,63.18 r90 top
R168 "R0603" R0603 126.68,59.37 r270 top
R169 "R0603" R0603 127.95,69.53 r0 top
R170 "R0603" R0603 127.95,72.07 r180 top
R171 "R0603" R0603 124.14,73.34 r90 top
R172 "R0603" R0603 121.6,59.37 r90 top
R173 "R2512" R2512 126.68,80.96 r90 top
R174 "R0603" R0603 119.06,63.18 r90 top
R175 "R0603" R0603 116.52,63.18 r90 top
R176 "R0603" R0603 163.51,63.18 r90 top
R177 "R0603" R0603 163.51,59.37 r270 top
R178 "R0603" R0603 164.78,69.53 r0 top
R179 "R0603" R0603 164.78,72.07 r180 top
R180 "R0603" R0603 160.97,73.34 r90 top
R181 "R0603" R0603 158.43,59.37 r90 top
R182 "R2512" R2512 163.51,80.96 r90 top
R183 "R0603" R0603 155.89,63.18 r90 top
R184 "R0603" R0603 153.35,63.18 r90 top
R185 "R1206" R1206 73.34,28.255 r0 top
R186 "R0603" R0603 147,126.68 r180 top
R187 "R0603" R0603 76.515,68.26 r270 top
R188 "R0603" R0603 73.34,70.8 r180 top
R189 "R0603" R0603 113.345,68.26 r270 top
R190 "R0603" R0603 110.17,70.8 r180 top
R191 "R0603" R0603 150.175,68.26 r270 top
R192 "R0603" R0603 147,70.8 r180 top
SJ1 "SJ_2" SJ_2 30.16,129.22 r90 top
SJ2 "SJ_2" SJ_2 66.99,129.22 r90 top
SJ3 "SJ_2" SJ_2 103.82,129.22 r90 top
SJ4 "SJ_2" SJ_2 140.65,129.22 r90 top
SJ5 "SJ_2" SJ_2 66.99,73.34 r90 top
SJ6 "SJ_2" SJ_2 103.82,73.34 r90 top
SJ7 "SJ_2" SJ_2 140.65,73.34 r90 top
SJ8 "SJ_2" SJ_2 84.77,47.94 r90 top
SJ9 "SJ_2" SJ_2 73.34,47.94 r90 top
SW1 "SS-12SDP2" SS-12SDP2 47.94,28.89 r90 top
U1 "20-TQFN" 20-TQFN 47.94,124.14 r0 top
U3 "PS-8" PS-8 47.94,39.05 r180 top
U5 "20-TQFN" 20-TQFN 84.77,124.14 r0 top
U6 "20-TQFN" 20-TQFN 121.6,124.14 r0 top
U7 "20-TQFN" 20-TQFN 158.43,124.14 r0 top
U8 "20-TQFN" 20-TQFN 84.77,68.26 r0 top
U9 "20-TQFN" 20-TQFN 121.6,68.26 r0 top
U10 "20-TQFN" 20-TQFN 158.43,68.26 r0 top
ZD44 "ZD-16V" ZD-16V 40.32,47.94 r180 top
ZD45 "ZD-16V" ZD-16V 45.4,47.94 r0 top
ZD46 "ZD-16V" ZD-16V 50.48,47.94 r180 top
ZD47 "ZD-16V" ZD-16V 55.56,47.94 r0 top
ZD55 "USC" USC 36.51,129.22 r180 top
ZD56 "USC" USC 73.34,129.22 r180 top
ZD57 "USC" USC 110.17,129.22 r180 top
ZD58 "USC" USC 147,129.22 r180 top
ZD59 "USC" USC 73.34,73.34 r180 top
ZD60 "USC" USC 110.17,73.34 r180 top
ZD61 "USC" USC 147,73.34 r180 top

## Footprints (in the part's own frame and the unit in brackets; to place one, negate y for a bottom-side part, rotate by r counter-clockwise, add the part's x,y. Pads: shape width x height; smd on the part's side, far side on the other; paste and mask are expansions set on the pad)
20-TQFN [mm] "KC00080BKP"
  rect 0.3x0.95 smd paste-1.153 mask+0: 1(-1,-1.84) 2(-0.5,-1.84) 3(0,-1.84) 4(0.5,-1.84) 5(1,-1.84) 11(1,1.84) 12(0.5,1.84) 13(0,1.84) 14(-0.5,1.84) 15(-1,1.84)
  rect 0.95x0.3 smd paste-1.153 mask+0: 6(1.84,-1) 7(1.84,-0.5) 8(1.84,0) 9(1.84,0.5) 10(1.84,1) 16(-1.84,1) 17(-1.84,0.5) 18(-1.84,0) 19(-1.84,-0.5) 20(-1.84,-1)
  rect 2.23x2.23 smd paste-2.433 mask+0: EP(0,0)
  silkscreen extent -2,-2 2,2
B2B-XH-A [mm] "KC00080BKP"
  round 1.5 hole 1 paste-1.7 mask+0: 1(-1.27,0) 2(1.27,0)
  silkscreen extent -3.7,-2.35 3.7,3.4
B2PS-VH [mm] "KC00080BKP"
  oval 2.55x5.1 / inner round 2.55 / far side oval 2.55x5.1 hole 1.7 paste-5.303 mask+0: P_1(-1.98,0) P_2(1.98,0)
  silkscreen extent -3.93,2.7 3.93,14.9
C0603K [mm] "KC00080BKP"
  rect 1.05x1.08 smd paste-1.283 mask+0: 1(-0.875,0) 2(0.875,0)
  silkscreen extent -0.72,-0.75 0.72,0.75
C0805K [mm] "KC00080BKP"
  rect 1.3x1.6 smd paste-1.803 mask+0: 1(-1,0) 2(1,0)
  silkscreen extent -0.92,-1 0.92,1
C1210K [mm] "KC00080BKP"
  rect 1.5x2.9 smd paste-3.103 mask+0: 1(-1.5,0) 2(1.5,0)
  silkscreen extent -1.52,-1.68 1.53,1.68
CLF12577NI-D [mm] "KC00080BKP"
  rect 4.5x4.2 smd paste-4.703 mask+0: 1(-5.35,0) 2(5.35,0)
  silkscreen extent -6.4,-6.25 6.4,6.25
CT [mm] "KC00080BKP"
  round 1.5 hole 1 paste-1.7 mask+0: P_1(0,0)
  silkscreen extent -1,-1 1,1
CTK03280ATP [mm] "KC00080BKP"
  round 1.397 hole 1 paste-1.397 mask+0: 1(0,0) 2(0,-2) 3(2,0) 4(2,-2) 5(4,0) 6(4,-2) 7(6,0) 8(6,-2) 9(8,0) 10(8,-2)
  silkscreen extent -2.6,-9.65 10.6,1.15
M-FLAT [mm] "KC00080BKP"
  rect 1.4x2.1 smd paste-2.303 mask+0: A(-2.2,0) C(2.2,0)
  silkscreen extent -1.9,-1.2 1.9,1.2
PS-8 [mm] "KC00080BKP"
  rect 0.4x0.65 smd paste-0.853 mask+0: 1(-0.975,-1.2) 2(-0.325,-1.2) 3(0.325,-1.2) 4(0.975,-1.2) 5(0.975,1.2) 6(0.325,1.2) 7(-0.325,1.2) 8(-0.975,1.2)
  silkscreen extent -1.45,-1.2 1.45,1.2
R0603 [mm] "KC00080BKP"
  rect 1x1.1 smd paste-1.303 mask+0: 1(-0.85,0) 2(0.85,0)
  silkscreen extent -0.43,-0.76 0.43,0.76
R1206 [mm] "KC00080BKP"
  rect 1.6x1.803 smd paste-2.006 mask+0: 1(-1.422,0) 2(1.422,0)
  silkscreen extent -0.97,-1.21 0.95,1.21
R2512 [mm] "KC00080BKP"
  rect 1.8x3.2 smd paste-3.403 mask+0: 1(-2.8,0) 2(2.8,0)
  silkscreen extent -2.36,-1.87 2.39,1.87
SJ_2 [mil] "KC00080BKP"
  rect 46x63 smd paste-71 mask+0: 1(-60,0) 2(0,0) 3(60,0)
  silkscreen extent -95,-40 95,40
SS-12SDP2 [mm] "KC00080BKP"
  round 1.35 hole 0.9 paste-1.55 mask+0: 1(0,2.54) 2(0,0) 3(0,-2.54)
  silkscreen extent -2,-5.1 2,5.1
TB9005FNG [mm] "KC00080BKP"
  rect 0.4x1.45 smd paste-1.653 mask+0: 1(-2.925,-2.8) 2(-2.275,-2.8) 3(-1.625,-2.8) 4(-0.975,-2.8) 5(-0.325,-2.8) 6(0.325,-2.8) 7(0.975,-2.8) 8(1.625,-2.8) 9(2.275,-2.8) 10(2.925,-2.8) 11(2.925,2.8) 12(2.275,2.8) 13(1.625,2.8) 14(0.975,2.8) 15(0.325,2.8) 16(-0.325,2.8) 17(-0.975,2.8) 18(-1.625,2.8) 19(-2.275,2.8) 20(-2.925,2.8)
  silkscreen extent -3.63,-4.9 3.5,2.2
TSON_ADVANCE_WF_ [mm] "KC00080BKP"
  rect 0.5x0.9 smd paste-1.103 mask+0: 1(-0.975,-0.85) 2(-0.325,-0.85) 3(0.325,-0.85) 4(0.975,-0.85) 5(0.975,2.25) 6(0.325,2.25) 7(-0.325,2.25) 8(-0.975,2.25)
  rect 2.65x2.3 smd paste-2.853 mask+0: EP(0,1.15)
  silkscreen extent -2.6,-1.8 1.55,2.25
TSOP6F [mm] "KC00080BKP"
  rect 0.62x0.7 smd paste-0.903 mask+0: 1(-0.95,-1.25) 2(0,-1.25) 3(0.95,-1.25) 4(0.95,1.25) 5(0,1.25) 6(-0.95,1.25)
  silkscreen extent -2.5,-2.25 1.45,1.1
TTA005 [mm] "KC00080BKP"
  rect 1.6x3 smd paste-3.203 mask+0: B(-2.3,-3.5) E(2.3,-3.5)
  rect 6x6 smd paste-6.203 mask+0: C(0,3)
  silkscreen extent -3.25,-1.75 3.25,3.75
UD-6_3X5_8_NICHICON [mm] "KC00080BKP"
  rect 2.8x1 smd paste-3.003 mask+0: 1(2.35,0) 2(-2.35,0)
  silkscreen extent -3.25,-3.25 3.25,3.25
USC [mm] "KC00080BKP"
  rect 0.8x0.9 smd paste-1.103 mask+0: A(1.15,0) K(-1.15,0)
  silkscreen extent -0.85,-0.63 0.85,0.63
ZD-16V [mm] "KC00080BKP"
  rect 1.2x1.2 smd paste-1.403 mask+0: A(-1.4,0) C(1.4,0)
  silkscreen extent -1.3,-0.8 1.3,0.8

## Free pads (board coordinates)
  round 0 hole 3.2 unplated paste-3.5 mask+0: ""(24.27,24.27) ""(24.27,168.27) ""(168.27,24.27) ""(168.27,168.27)

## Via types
v1: diameter 0.7, hole 0.3, TOP to BOTTOM, tented both sides, 257 vias
v2: diameter 0.9, hole 0.5, TOP to BOTTOM, 9 vias

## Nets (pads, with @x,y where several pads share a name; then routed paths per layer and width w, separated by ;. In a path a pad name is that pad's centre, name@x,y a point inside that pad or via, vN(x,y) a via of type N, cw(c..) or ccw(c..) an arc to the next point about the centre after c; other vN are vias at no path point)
+5V: C68.1 C71.1 CON1.1 IC4.7 IC4.8 Q81.C R126.2 SJ8.1 SJ9.1 SW1.3 | length 79.9
  TOP w0.254: R126.2@47.94,33.12 47.94,31.43 SW1.3@50.48,28.89 55.56,23.81 87.31,23.81 88.58,25.08 88.58,26.35 ; v1(73.34,44.13) SJ9.1@73.34,46.416 ; IC4.7@80.665,37.52 80.665,36.17 81.595,35.24 82.23,35.24 81.315,36.155 IC4.8@81.315,37.52 ; 84.77,33.97 v1(84.77,42.86) SJ8.1@84.77,46.416
  Mid-Layer 1 w0.254: v1(73.34,44.13) 83.5,44.13 v1(84.77,42.86)
+12V: C21.1 C70.1 CON9.P_1 IC4.1 Q73.5 Q73.6 Q73.7 Q73.8 Q73.EP R185.1 U3.1 | length 20.3
  TOP w0.254: U3.1@48.915,40.25 51.425,40.25 C21.1@51.75,39.925 55.955,39.925 60.64,35.24 ; 72.07,35.24 75.88,35.24 76.765,36.125 IC4.1@76.765,37.52
  other v1: 60.64,27.62 61.91,27.62 63.18,27.62 64.45,27.62 60.64,28.89 61.91,28.89 63.18,28.89 64.45,28.89 60.64,30.16 61.91,30.16 63.18,30.16 64.45,30.16 60.64,31.43 61.91,31.43 63.18,31.43 64.45,31.43
GND: C1.1 C2.1 C3.1 C4.1 C5.1 C18.1 C19.1 C21.2 C26.1 C27.1 C28.1 C29.1 C32.1 C33.1 C34.1 C35.1 C36.1 C39.1 C40.1 C41.1 C42.1 C43.1 C46.1 C47.1 C48.1 C49.1 C50.1 C53.1 C54.1 C55.1 C56.1 C57.1 C60.1 C61.1 C62.1 C63.1 C64.1 C67.1 C69.2 C70.2 C71.2 C72.1 C73.1 C74.1 C75.1 C76.1 CON1.2 CON9.P_2 CON10.5 CON10.10 IC4.10 IC4.14 IC4.16 IC4.20 R2.1 R3.2 R5.2 R7.1 R8.1 R23.1 R38.1 R53.1 R68.1 R83.1 R98.1 R113.1 R125.1 R132.2 R133.2 R134.1 R136.1 R137.1 R141.2 R142.2 R143.1 R145.1 R146.1 R150.2 R151.2 R152.1 R154.1 R155.1 R159.2 R160.2 R161.1 R163.1 R164.1 R168.2 R169.2 R170.1 R172.1 R173.1 R177.2 R178.2 R179.1 R181.1 R182.1 SJ1.1 SJ2.1 SJ3.1 SJ4.1 SJ5.1 SJ6.1 SJ7.1 SJ8.3 SJ9.3 U1.2 U1.12 U1.EP U3.2 U3.5 U5.2 U5.12 U5.EP U6.2 U6.12 U6.EP U7.2 U7.12 U7.EP U8.2 U8.12 U8.EP U9.2 U9.12 U9.EP U10.2 U10.12 U10.EP | length 86.6
  TOP w0.254: 46.67,119.695 46.67,120.33 47.44,121.1 U1.2@47.44,122.3 47.44,123.64 U1.EP@47.94,124.14 ; 47.94,134.3 48.44,133.8 U1.12@48.44,125.98 ; 83.5,63.815 83.5,64.45 84.27,65.22 U8.2@84.27,66.42 84.27,67.76 U8.EP@84.77,68.26 ; 83.5,119.695 83.5,120.33 84.27,121.1 U5.2@84.27,122.3 84.27,123.64 U5.EP@84.77,124.14 ; 84.77,78.42 85.27,77.92 U8.12@85.27,70.1 ; 84.77,134.3 85.27,133.8 U5.12@85.27,125.98 ; 120.33,63.815 120.33,64.45 121.1,65.22 U9.2@121.1,66.42 121.1,67.76 U9.EP@121.6,68.26 ; 120.33,119.695 120.33,120.33 121.1,121.1 U6.2@121.1,122.3 121.1,123.64 U6.EP@121.6,124.14 ; 121.6,78.42 122.1,77.92 U9.12@122.1,70.1 ; 121.6,134.3 122.1,133.8 U6.12@122.1,125.98 ; 157.16,63.815 157.16,64.45 157.93,65.22 U10.2@157.93,66.42 157.93,67.76 U10.EP@158.43,68.26 ; 157.16,119.06 157.16,120.33 157.93,121.1 U7.2@157.93,122.3 157.93,123.64 U7.EP@158.43,124.14 ; 158.43,134.3 158.93,133.8 U7.12@158.93,125.98
  other v1: 65.72,59.37 73.34,59.37 102.55,59.37 110.17,59.37 139.38,59.37 147,59.37 80.96,101.28 117.79,101.28 154.62,101.28 139.38,115.25 147,115.25 35.24,124.14 72.07,124.14 44.13,157.16 80.96,157.16 117.79,157.16 154.62,157.16
LED+1: C3.2 C18.2 CON2.2 D1.C R4.2 R118.2 | length 46.8
  TOP w0.254: D1.C@37.78,153.01 38.12,153.35 v1(40.32,153.35) ; R118.2@39.685,123.29 v1(39.685,121.6) 41.375,119.91 R4.2@42.86,119.91
  TOP w1.676: CON2.2@38.415,167.32 38.415,161.375 C18.2@38.82,160.97
  Mid-Layer 2 w0.254: v1(39.685,121.6) 40.32,122.235 v1(40.32,153.35)
LED+2: C19.2 C32.2 CON3.2 D48.C R120.2 R139.2 | length 46.8
  TOP w0.254: D48.C@74.61,153.01 74.95,153.35 v1(77.15,153.35) ; R120.2@76.515,123.29 v1(76.515,121.6) 78.205,119.91 R139.2@79.69,119.91
  TOP w1.676: CON3.2@75.245,167.32 75.245,161.375 C32.2@75.65,160.97
  Mid-Layer 2 w0.254: v1(76.515,121.6) 77.15,122.235 v1(77.15,153.35)
LED+3: C39.2 C46.2 CON4.2 D49.C R122.2 R148.2 | length 46.8
  TOP w0.254: D49.C@111.44,153.01 111.78,153.35 v1(113.98,153.35) ; R122.2@113.345,123.29 v1(113.345,121.6) 115.035,119.91 R148.2@116.52,119.91
  TOP w1.676: CON4.2@112.075,167.32 112.075,161.375 C46.2@112.48,160.97
  Mid-Layer 2 w0.254: v1(113.345,121.6) 113.98,122.235 v1(113.98,153.35)
LED+4: C53.2 C60.2 CON5.2 D50.C R124.2 R157.2 | length 46.8
  TOP w0.254: D50.C@148.27,153.01 148.61,153.35 v1(150.81,153.35) ; R124.2@150.175,123.29 v1(150.175,121.6) 151.865,119.91 R157.2@153.35,119.91
  TOP w1.676: CON5.2@148.905,167.32 148.905,161.375 C60.2@149.31,160.97
  Mid-Layer 2 w0.254: v1(150.175,121.6) 150.81,122.235 v1(150.81,153.35)
LED+5: C75.2 C76.2 CON6.2 D51.C R166.2 R187.2 | length 46.8
  TOP w0.254: D51.C@74.61,97.13 74.95,97.47 v1(77.15,97.47) ; R187.2@76.515,67.41 v1(76.515,65.72) 78.205,64.03 R166.2@79.69,64.03
  TOP w1.676: CON6.2@75.245,111.44 75.245,105.495 C76.2@75.65,105.09
  Mid-Layer 2 w0.254: v1(76.515,65.72) 77.15,66.355 v1(77.15,97.47)
LED+6: C67.2 C72.2 CON7.2 D52.C R175.2 R189.2 | length 46.8
  TOP w0.254: D52.C@111.44,97.13 111.78,97.47 v1(113.98,97.47) ; R189.2@113.345,67.41 v1(113.345,65.72) 115.035,64.03 R175.2@116.52,64.03
  TOP w1.676: CON7.2@112.075,111.44 112.075,105.495 C72.2@112.48,105.09
  Mid-Layer 2 w0.254: v1(113.345,65.72) 113.98,66.355 v1(113.98,97.47)
LED+7: C73.2 C74.2 CON8.2 D53.C R184.2 R191.2 | length 45.1
  TOP w0.254: R191.2@150.175,67.41 v1(150.175,65.72) 150.175,65.085 151.23,64.03 R184.2@153.35,64.03 ; 150.175,97.47 v1(150.81,97.47)
  TOP w1.676: CON8.2@148.905,111.44 148.905,105.495 C74.2@149.31,105.09
  Mid-Layer 2 w0.254: v1(150.175,65.72) 150.81,66.355 v1(150.81,97.47)
LED-1: CON2.1 Q2.1 Q2.2 Q2.5 Q2.6 | length 10.6
  TOP w1.676: CON2.1@40.955,167.32 44.13,167.32 46.67,164.78 46.67,160.97
LED-2: CON3.1 Q12.1 Q12.2 Q12.5 Q12.6 | length 9.9
  TOP w1.676: CON3.1@77.785,167.32 80.96,167.32 83.5,164.78 83.5,161.605
LED-3: CON4.1 Q22.1 Q22.2 Q22.5 Q22.6 | length 9.3
  TOP w1.676: CON4.1@114.615,167.32 117.79,167.32 120.33,164.78 120.33,162.24
LED-4: CON5.1 Q32.1 Q32.2 Q32.5 Q32.6 | length 9.9
  TOP w1.676: CON5.1@151.445,167.32 154.62,167.32 157.16,164.78 157.16,161.605
LED-5: CON6.1 Q42.1 Q42.2 Q42.5 Q42.6 | length 9.3
  TOP w1.676: CON6.1@77.785,111.44 80.96,111.44 83.5,108.9 83.5,106.36
LED-6: CON7.1 Q52.1 Q52.2 Q52.5 Q52.6 | length 9.3
  TOP w1.676: CON7.1@114.615,111.44 117.79,111.44 120.33,108.9 120.33,106.36
LED-7: CON8.1 Q62.1 Q62.2 Q62.5 Q62.6 | length 9.9
  TOP w1.676: CON8.1@151.445,111.44 154.62,111.44 157.16,108.9 157.16,105.725
LV1: C6.1 C8.1 R9.1 R22.1 SJ1.2 U1.19 | length 8.1
  TOP w0.254: 42.86,121.6 C6.1@42.86,123.265 ; v1(43.495,121.6) 45.535,123.64 U1.19@46.1,123.64 ; v1(45.4,117.155) R9.1@45.4,118.21
  Mid-Layer 1 w0.254: 43.495,117.155 v1(45.4,117.155)
  other v1: 42.225,121.6 26.985,129.22 28.255,129.22 32.065,129.22 33.335,129.22 52.385,147.635 53.655,147.635 54.925,147.635 52.385,148.905 53.655,148.905 54.925,148.905 52.385,150.175 53.655,150.175 54.925,150.175
LV2: C9.1 C31.1 R37.1 R138.1 SJ2.2 U5.19 | length 8.1
  TOP w0.254: 79.69,121.6 C31.1@79.69,123.265 ; v1(80.325,121.6) 82.365,123.64 U5.19@82.93,123.64 ; v1(82.23,117.155) R138.1@82.23,118.21
  Mid-Layer 1 w0.254: 80.325,117.155 v1(82.23,117.155)
  other v1: 79.055,121.6 63.815,129.22 65.085,129.22 68.895,129.22 70.165,129.22 89.215,147.635 90.485,147.635 91.755,147.635 89.215,148.905 90.485,148.905 91.755,148.905 89.215,150.175 90.485,150.175 91.755,150.175
LV3: C10.1 C38.1 R52.1 R147.1 SJ3.2 U6.19 | length 8.1
  TOP w0.254: 116.52,121.6 C38.1@116.52,123.265 ; v1(117.155,121.6) 119.195,123.64 U6.19@119.76,123.64 ; v1(119.06,117.155) R147.1@119.06,118.21
  Mid-Layer 1 w0.254: 117.155,117.155 v1(119.06,117.155)
  other v1: 115.885,121.6 100.645,129.22 101.915,129.22 105.725,129.22 106.995,129.22 126.045,147.635 127.315,147.635 128.585,147.635 126.045,148.905 127.315,148.905 128.585,148.905 126.045,150.175 127.315,150.175 128.585,150.175
LV4: C11.1 C45.1 R67.1 R156.1 SJ4.2 U7.19 | length 8.1
  TOP w0.254: 153.35,121.6 C45.1@153.35,123.265 ; v1(153.985,121.6) 156.025,123.64 U7.19@156.59,123.64 ; v1(155.89,117.155) R156.1@155.89,118.21
  Mid-Layer 1 w0.254: 153.985,117.155 v1(155.89,117.155)
  other v1: 152.715,121.6 137.475,129.22 138.745,129.22 142.555,129.22 143.825,129.22 162.875,147.635 164.145,147.635 165.415,147.635 162.875,148.905 164.145,148.905 165.415,148.905 162.875,150.175 164.145,150.175 165.415,150.175
LV5: C12.1 C52.1 R82.1 R165.1 SJ5.2 U8.19 | length 8.1
  TOP w0.254: 79.69,65.72 C52.1@79.69,67.385 ; v1(80.325,65.72) 82.365,67.76 U8.19@82.93,67.76 ; v1(82.23,61.275) R165.1@82.23,62.33
  Mid-Layer 1 w0.254: 80.325,61.275 v1(82.23,61.275)
  other v1: 79.055,65.72 63.815,73.34 65.085,73.34 68.895,73.34 70.165,73.34 89.215,91.755 90.485,91.755 91.755,91.755 89.215,93.025 90.485,93.025 91.755,93.025 89.215,94.295 90.485,94.295 91.755,94.295
LV6: C13.1 C59.1 R97.1 R174.1 SJ6.2 U9.19 | length 8.1
  TOP w0.254: 116.52,65.72 C59.1@116.52,67.385 ; v1(117.155,65.72) 119.195,67.76 U9.19@119.76,67.76 ; v1(119.06,61.275) R174.1@119.06,62.33
  Mid-Layer 1 w0.254: 117.155,61.275 v1(119.06,61.275)
  other v1: 115.885,65.72 100.645,73.34 101.915,73.34 105.725,73.34 106.995,73.34 126.045,91.755 127.315,91.755 128.585,91.755 126.045,93.025 127.315,93.025 128.585,93.025 126.045,94.295 127.315,94.295 128.585,94.295
LV7: C14.1 C66.1 R112.1 R183.1 SJ7.2 U10.19 | length 8.7
  TOP w0.254: C66.1@153.35,67.385 153.35,65.72 v1(153.985,65.72) 156.025,67.76 U10.19@156.59,67.76 ; v1(155.89,61.275) R183.1@155.89,62.33
  Mid-Layer 1 w0.254: 153.985,61.275 v1(155.89,61.275)
  other v1: 152.715,65.72 137.475,73.34 138.745,73.34 142.555,73.34 143.825,73.34 162.875,91.755 164.145,91.755 165.415,91.755 162.875,93.025 164.145,93.025 165.415,93.025 162.875,94.295 164.145,94.295 165.415,94.295
N_1: R5.1 R6.1 U1.5 | length 12.6
  TOP w0.254: U1.5@48.94,122.3 48.94,121.87 49.21,121.6 53.02,121.6 54.29,120.33 54.29,117.79 53.655,117.155 53.02,117.155 ; R5.1@53.02,116.1 53.02,117.155 ; R6.1@53.02,118.21 53.02,117.155
N_2: C4.2 R6.2 U1.4 | length 6.3
  TOP w0.254: U1.4@48.44,122.3 48.44,121.1 49.21,120.33 50.085,120.33 C4.2@50.48,119.935 ; C4.2@50.48,119.91 R6.2@53.02,119.91
N_3: C5.2 U1.14 | length 2.6
  TOP w0.254: C5.2@46.67,128.22 47.44,127.45 U1.14@47.44,125.98
N_4: R3.1 U1.8 | length 4.2
  TOP w0.254: U1.8@49.78,124.14 51.115,124.14 52.385,125.41 R3.1@53.44,125.41
N_5: C2.2 U1.6 | length 3.7
  TOP w0.254: U1.6@49.78,123.14 51.48,123.14 51.75,122.87 C2.2@53.415,122.87
N_6: R1.1 R2.2 U1.9 | length 7.6
  TOP w0.254: U1.9@49.78,124.64 50.345,124.64 51.75,126.045 51.75,127.95 ; R1.1@50.48,128.37 51.33,128.37 51.75,127.95 ; R2.2@53.44,127.95 51.75,127.95
N_7: Q1.4 U1.13 | length 23.3
  TOP w0.254: v1(46.67,133.03) 47.94,131.76 U1.13@47.94,125.98 ; Q1.4@50.06,144.165 50.82,144.165 51.115,144.46 v1(51.115,145.095)
  Mid-Layer 2 w0.254: v1(46.67,133.03) 46.67,140.65 v1(51.115,145.095)
N_8: D1.A L1.2 Q1.5 Q1.6 Q1.7 Q1.8 Q1.EP
N_9: Q1.1 Q1.2 Q1.3 R8.2 U1.11 | length 16.7
  TOP w0.254: U1.11@48.94,125.98 48.94,137.84 50.48,139.38 52.76,139.38 R8.2@53.02,139.64
N_10: C7.2 U1.3 | length 2.4
  TOP w0.254: C7.2@47.94,119.935 U1.3@47.94,122.3
N_11: C7.1 R7.2 | length 2.1
  TOP w0.254: R7.2@47.94,116.1 C7.1@47.94,118.185
N_12: R4.1 R9.2 U1.1 | length 7
  TOP w0.254: R4.1@42.86,118.21 43.915,118.21 44.13,118.425 44.13,119.695 44.345,119.91 R9.2@45.4,119.91 46.94,121.45 U1.1@46.94,122.3
N_13: C6.2 U1.17 | length 3.4
  TOP w0.254: C6.2@42.86,125.015 43.89,125.015 44.265,124.64 U1.17@46.1,124.64
N_14: Q73.4 Q74.4 R128.2 R129.2 R130.1 ZD44.C ZD47.C | length 47.9
  TOP w0.254: v1(39.05,50.48) ZD44.C@39.05,48.07 ; v1(44.765,55.56) 44.98,55.345 Q73.4@44.98,53.995 ; Q74.4@50.9,52.045 50.9,50.695 51.75,49.845 56.195,49.845 56.83,49.21 56.83,48.07 ZD47.C@56.96,47.94 56.83,47.81 56.83,46.67 55.56,45.4 R130.1@51.33,45.4 51.33,43.71 50.48,42.86 R128.2@48.79,42.86 47.52,44.13 45.4,44.13 44.55,44.98 R129.2@44.55,45.4 40.32,45.4 39.05,46.67 ZD44.C@39.05,48.07 ; ZD44.C@39.05,48.07 ZD44.C@38.92,47.94 ZD44.C@39.05,48.07
  Mid-Layer 2 w0.254: v1(39.05,50.48) 39.05,53.02 41.59,55.56 v1(44.765,55.56)
N_15: Q2.3 R23.2 R24.1 | length 9.1
  TOP w0.254: R23.2@44.13,152.5 45.185,152.5 45.4,152.715 45.4,153.985 45.615,154.2 R24.1@46.67,154.2 46.67,156.525 45.42,157.775 Q2.3@45.42,158.75
N_16: C26.2 R131.2 U5.4 | length 6.3
  TOP w0.254: U5.4@85.27,122.3 85.27,121.1 86.04,120.33 86.915,120.33 C26.2@87.31,119.935 ; C26.2@87.31,119.91 R131.2@89.85,119.91
N_18: C33.2 R140.2 U6.4 | length 6.3
  TOP w0.254: U6.4@122.1,122.3 122.1,121.1 122.87,120.33 123.745,120.33 C33.2@124.14,119.935 ; C33.2@124.14,119.91 R140.2@126.68,119.91
N_19: C40.2 R149.2 U7.4 | length 6.3
  TOP w0.254: U7.4@158.93,122.3 158.93,121.1 159.7,120.33 160.575,120.33 C40.2@160.97,119.935 ; C40.2@160.97,119.91 R149.2@163.51,119.91
N_20: C47.2 R158.2 U8.4 | length 6.3
  TOP w0.254: U8.4@85.27,66.42 85.27,65.22 86.04,64.45 86.915,64.45 C47.2@87.31,64.055 ; C47.2@87.31,64.03 R158.2@89.85,64.03
N_21: C61.2 R176.2 U10.4 | length 6.3
  TOP w0.254: U10.4@158.93,66.42 158.93,65.22 159.7,64.45 160.575,64.45 C61.2@160.97,64.055 ; C61.2@160.97,64.03 R176.2@163.51,64.03
N_22: C54.2 R167.2 U9.4 | length 6.3
  TOP w0.254: U9.4@122.1,66.42 122.1,65.22 122.87,64.45 123.745,64.45 C54.2@124.14,64.055 ; C54.2@124.14,64.03 R167.2@126.68,64.03
N_36: R24.2 U1.18 | length 32.8
  TOP w0.254: v1(44.13,123.505) 44.765,124.14 U1.18@46.1,124.14 ; v1(46.67,150.81) R24.2@46.67,152.5
  Mid-Layer 2 w0.254: v1(44.13,123.505) 43.495,124.14 43.495,147.635 v1(46.67,150.81)
N_54: IC4.2 Q81.E R185.2 | length 9.3
  TOP w0.254: 75.88,28.89 75.88,33.97 77.415,35.505 IC4.2@77.415,37.52
N_55: Q12.3 R38.2 R39.1 | length 9.1
  TOP w0.254: R38.2@80.96,152.5 82.015,152.5 82.23,152.715 82.23,153.985 82.445,154.2 R39.1@83.5,154.2 83.5,155.89 82.25,157.14 Q12.3@82.25,158.75
N_75: C68.2 IC4.5 | length 4.6
  TOP w0.254: IC4.5@79.365,37.52 79.365,34.295 79.69,33.97 C68.2@80.595,33.97
N_76: Q22.3 R53.2 R54.1 | length 9.1
  TOP w0.254: R53.2@117.79,152.5 118.845,152.5 119.06,152.715 119.06,153.985 119.275,154.2 R54.1@120.33,154.2 120.33,156.525 119.08,157.775 Q22.3@119.08,158.75
N_77: IC4.3 Q81.B | length 6.6
  TOP w0.254: IC4.3@78.065,37.52 78.065,34.325 78.73,33.66 Q81.B@78.73,31.19
N_96: C69.1 IC4.15 | length 4
  TOP w0.254: C69.1@79.69,46.94 79.69,45.4 80.015,45.075 IC4.15@80.015,43.12
N_97: Q32.3 R68.2 R69.1 | length 9.1
  TOP w0.254: R68.2@154.62,152.5 155.675,152.5 155.89,152.715 155.89,153.985 156.105,154.2 R69.1@157.16,154.2 157.16,156.525 155.91,157.775 Q32.3@155.91,158.75
N_117: IC4.13 SJ8.2 | length 7.7
  TOP w0.254: IC4.13@81.315,43.12 81.315,47.025 82.23,47.94 SJ8.2@84.77,47.94
N_118: Q42.3 R83.2 R84.1 | length 9.1
  TOP w0.254: R83.2@80.96,96.62 82.015,96.62 82.23,96.835 82.23,98.105 82.445,98.32 R84.1@83.5,98.32 83.5,100.645 82.25,101.895 Q42.3@82.25,102.87
N_138: IC4.19 SJ9.2 | length 8
  TOP w0.254: SJ9.2@73.34,47.94 75.88,47.94 77.415,46.405 IC4.19@77.415,43.12
N_139: Q52.3 R98.2 R99.1 | length 9.1
  TOP w0.254: R98.2@117.79,96.62 118.845,96.62 119.06,96.835 119.06,98.105 119.275,98.32 R99.1@120.33,98.32 120.33,100.645 119.08,101.895 Q52.3@119.08,102.87
N_159: C14.2 Q62.4 R112.2 U10.20 | length 44
  TOP w0.254: v1(155.89,65.72) 155.89,66.99 156.16,67.26 U10.20@156.59,67.26 ; v1(160.97,100.01) 160.97,100.645
  Mid-Layer 2 w0.254: v1(155.89,65.72) 161.605,65.72 162.875,66.99 162.875,90.485 160.97,92.39 v1(160.97,100.01)
N_160: Q62.3 R113.2 R114.1 | length 8.9
  TOP w0.254: R113.2@154.62,96.62 155.675,96.62 155.89,96.835 155.89,97.788 156.422,98.32 R114.1@157.16,98.32 157.16,100.645 155.91,101.895 Q62.3@155.91,102.87
N_208: R120.1 R121.1 U5.16 ZD56.K | length 1.7
  TOP w0.254: 81.595,126.045 82.5,125.14 U5.16@82.93,125.14
N_209: C13.2 Q52.4 R97.2 U9.20 | length 44
  TOP w0.254: v1(119.06,65.72) 119.06,66.99 119.33,67.26 U9.20@119.76,67.26 ; v1(124.14,100.01) 124.14,100.645
  Mid-Layer 2 w0.254: v1(119.06,65.72) 124.775,65.72 126.045,66.99 126.045,89.85 124.14,91.755 v1(124.14,100.01)
N_210: R84.2 U8.18 | length 32.8
  TOP w0.254: v1(80.96,67.625) 81.595,68.26 U8.18@82.93,68.26 ; v1(83.5,94.93) R84.2@83.5,96.62
  Mid-Layer 2 w0.254: v1(80.96,67.625) 80.325,68.26 80.325,91.755 v1(83.5,94.93)
N_211: R39.2 U5.18 | length 32.8
  TOP w0.254: v1(80.96,123.505) 81.595,124.14 U5.18@82.93,124.14 ; v1(83.5,150.81) R39.2@83.5,152.5
  Mid-Layer 2 w0.254: v1(80.96,123.505) 80.325,124.14 80.325,147.635 v1(83.5,150.81)
N_212: R54.2 U6.18 | length 32.8
  TOP w0.254: v1(117.79,123.505) 118.425,124.14 U6.18@119.76,124.14 ; v1(120.33,150.81) R54.2@120.33,152.5
  Mid-Layer 2 w0.254: v1(117.79,123.505) 117.155,124.14 117.155,147.635 v1(120.33,150.81)
N_213: R69.2 U7.18 | length 32.8
  TOP w0.254: v1(154.62,123.505) 155.255,124.14 U7.18@156.59,124.14 ; v1(157.16,150.81) R69.2@157.16,152.5
  Mid-Layer 2 w0.254: v1(154.62,123.505) 153.985,124.14 153.985,147.635 v1(157.16,150.81)
N_214: C9.2 Q12.4 R37.2 U5.20 | length 44
  TOP w0.254: v1(82.23,121.6) 82.23,122.87 82.5,123.14 U5.20@82.93,123.14 ; v1(87.31,155.89) 87.31,156.525
  Mid-Layer 2 w0.254: v1(82.23,121.6) 87.945,121.6 89.215,122.87 89.215,145.73 87.31,147.635 v1(87.31,155.89)
N_215: R99.2 U9.18 | length 32.8
  TOP w0.254: v1(117.79,67.625) 118.425,68.26 U9.18@119.76,68.26 ; v1(120.33,94.93) R99.2@120.33,96.62
  Mid-Layer 2 w0.254: v1(117.79,67.625) 117.155,68.26 117.155,91.755 v1(120.33,94.93)
N_216: R114.2 U10.18 | length 32.8
  TOP w0.254: v1(154.62,67.625) 155.255,68.26 U10.18@156.59,68.26 ; v1(157.16,94.93) R114.2@157.16,96.62
  Mid-Layer 2 w0.254: v1(154.62,67.625) 153.985,68.26 153.985,91.755 v1(157.16,94.93)
N_217: C12.2 Q42.4 R82.2 U8.20 | length 44
  TOP w0.254: v1(82.23,65.72) 82.23,66.99 82.5,67.26 U8.20@82.93,67.26 ; v1(87.31,100.01) 87.31,100.645
  Mid-Layer 2 w0.254: v1(82.23,65.72) 87.945,65.72 89.215,66.99 89.215,89.85 87.31,91.755 v1(87.31,100.01)
N_218: C10.2 Q22.4 R52.2 U6.20 | length 44
  TOP w0.254: v1(119.06,121.6) 119.06,122.87 119.33,123.14 U6.20@119.76,123.14 ; v1(124.14,155.89) 124.14,156.525
  Mid-Layer 2 w0.254: v1(119.06,121.6) 124.775,121.6 126.045,122.87 126.045,145.73 124.14,147.635 v1(124.14,155.89)
N_219: R122.1 R123.1 U6.16 ZD57.K | length 1.7
  TOP w0.254: 118.425,126.045 119.33,125.14 U6.16@119.76,125.14
N_220: C8.2 Q2.4 R22.2 U1.20 | length 44
  TOP w0.254: v1(45.4,121.6) 45.4,122.87 45.67,123.14 U1.20@46.1,123.14 ; v1(50.48,155.89) 50.48,156.525
  Mid-Layer 2 w0.254: v1(45.4,121.6) 51.115,121.6 52.385,122.87 52.385,145.73 50.48,147.635 v1(50.48,155.89)
N_221: R118.1 R119.1 U1.16 ZD55.K | length 1.7
  TOP w0.254: 44.765,126.045 45.67,125.14 U1.16@46.1,125.14
N_222: R124.1 R186.1 U7.16 ZD58.K | length 1.7
  TOP w0.254: 155.255,126.045 156.16,125.14 U7.16@156.59,125.14
N_223: R187.1 R188.1 U8.16 ZD59.K | length 1.7
  TOP w0.254: 81.595,70.165 82.5,69.26 U8.16@82.93,69.26
N_224: R189.1 R190.1 U9.16 ZD60.K | length 1.7
  TOP w0.254: 118.425,70.165 119.33,69.26 U9.16@119.76,69.26
N_225: R191.1 R192.1 U10.16 ZD61.K | length 1.7
  TOP w0.254: 155.255,70.165 156.16,69.26 U10.16@156.59,69.26
N_231: R125.2 U3.8 | length 3.7
  TOP w0.254: U3.8@48.915,37.85 48.915,37.44 50.48,35.875 R125.2@50.48,34.82
N_232: R127.2 U3.6 | length 4.3
  TOP w0.254: R127.2@45.4,34.82 45.4,35.875 46.035,36.51 46.67,36.51 47.615,37.455 U3.6@47.615,37.85
N_234: R128.1 U3.3 | length 2.8
  TOP w0.254: R128.1@47.09,42.86 47.615,42.335 U3.3@47.615,40.25
N_235: Q73.1 Q73.2 Q73.3 Q74.1 Q74.2 Q74.3 R129.1 R130.2 ZD45.C ZD46.C
N_237: ZD44.A ZD45.A | length 2.3
  TOP w0.813: ZD44.A@41.72,47.94 ZD45.A@44,47.94
N_238: ZD46.A ZD47.A | length 2.3
  TOP w0.813: ZD46.A@51.88,47.94 ZD47.A@54.16,47.94
N_243: IC4.11 P23.P_1 | length 8.6
  TOP w0.254: IC4.11@82.615,43.12 82.615,45.15 v1(82.865,45.4)
  Mid-Layer 1 w0.254: v1(82.865,45.4) 87.31,45.4 P23.P_1@88.58,46.67
N_244: IC4.17 P24.P_1 | length 6.7
  TOP w0.254: P24.P_1@77.15,49.21 77.15,47.94 78.42,46.67 78.42,46.035 78.715,45.74 IC4.17@78.715,43.12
